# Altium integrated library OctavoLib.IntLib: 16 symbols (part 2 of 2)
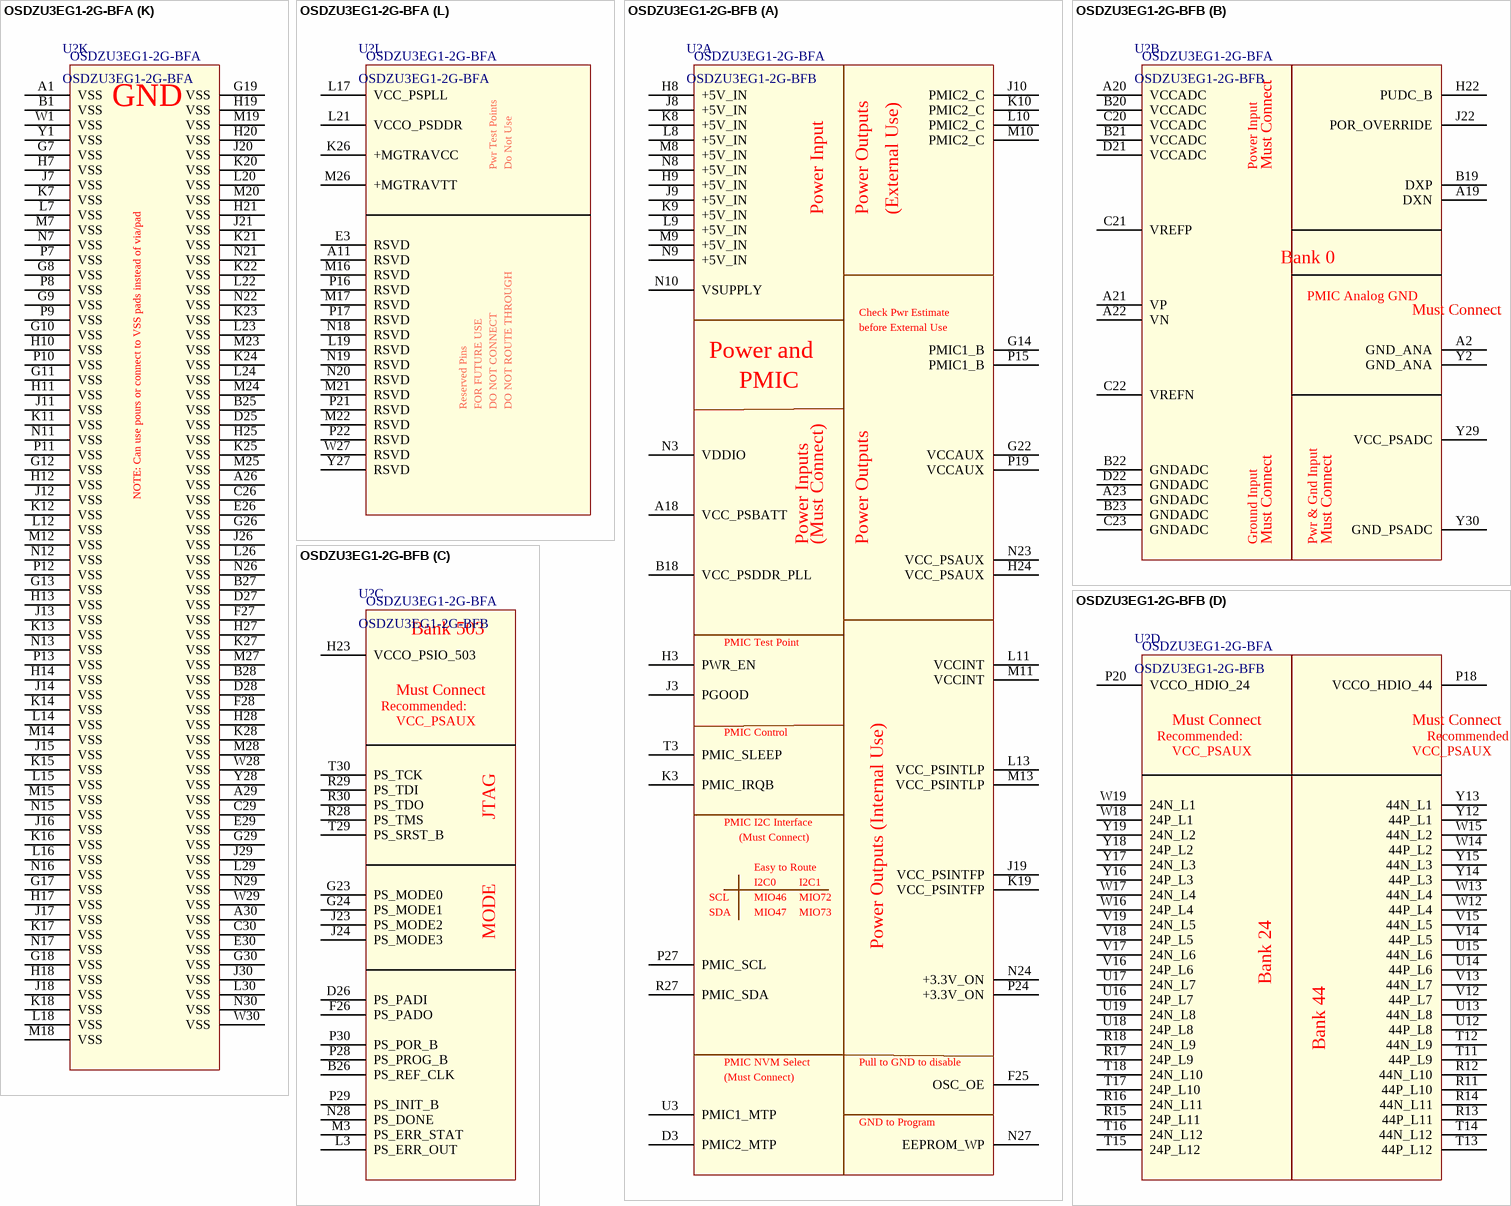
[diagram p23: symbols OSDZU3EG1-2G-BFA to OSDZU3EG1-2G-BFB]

## OSDZU3EG1-2G-BFA
designator U?
Octavo Systems LLC OSDZU3x Family SiP; 20.5mm x 40mm, 1mm pitch 600 pin BGA contains Xilinx XCZU3EG1, 2GB DDR4, two IRPS5401, 32MB QSPI NOR Flash (3.3V), MEMS Oscillator, RTC Crystal and passives; Commercial Temperature (case):  0C to 85C.
footprint BGA_20x30_600_1p00mm (600 pin 1mm pitch footprint)
part A pins: A18 VCC_PSBATT, B18 VCC_PSDDR_PLL, D3 PMIC2_MTP, F25 OSC_OE, G14 PMIC1_B, G22 VCCAUX, H3 PWR_EN, H8 +5V_IN, H9 +5V_IN, H24 VCC_PSAUX, J3 PGOOD, J8 +5V_IN, J9 +5V_IN, J10 PMIC2_C, J19 VCC_PSINTFP, K3 PMIC_IRQB, K8 +5V_IN, K9 +5V_IN, K10 PMIC2_C, K19 VCC_PSINTFP, L8 +5V_IN, L9 +5V_IN, L10 PMIC2_C, L11 VCCINT, L13 VCC_PSINTLP, M8 +5V_IN, M9 +5V_IN, M10 PMIC2_C, M11 VCCINT, M13 VCC_PSINTLP, N3 VDDIO, N8 +5V_IN, N9 +5V_IN, N10 VSUPPLY, N23 VCC_PSAUX, N24 +3.3V_ON, N27 EEPROM_WP, P15 PMIC1_B, P19 VCCAUX, P24 +3.3V_ON, P27 PMIC_SCL, R27 PMIC_SDA, T3 PMIC_SLEEP, U3 PMIC1_MTP
part B pins: A2 GND_ANA, A19 DXN, A20 VCCADC, A21 VP, A22 VN, A23 GNDADC, B19 DXP, B20 VCCADC, B21 VCCADC, B22 GNDADC, B23 GNDADC, C20 VCCADC, C21 VREFP, C22 VREFN, C23 GNDADC, D21 VCCADC, D22 GNDADC, H22 PUDC_B, J22 POR_OVERRIDE, Y2 GND_ANA, Y29 VCC_PSADC, Y30 GND_PSADC
part C pins: B26 PS_REF_CLK, D26 PS_PADI, F26 PS_PADO, G23 PS_MODE0, G24 PS_MODE1, H23 VCCO_PSIO_503, J23 PS_MODE2, J24 PS_MODE3, L3 PS_ERR_OUT, M3 PS_ERR_STAT, N28 PS_DONE, P28 PS_PROG_B, P29 PS_INIT_B, P30 PS_POR_B, R28 PS_TMS, R29 PS_TDI, R30 PS_TDO, T29 PS_SRST_B, T30 PS_TCK
part D pins: P18 VCCO_HDIO_44, P20 VCCO_HDIO_24, R11 44P_L10, R12 44N_L10, R13 44P_L11, R14 44N_L11, R15 24P_L11, R16 24N_L11, R17 24P_L9, R18 24N_L9, T11 44P_L9, T12 44N_L9, T13 44P_L12, T14 44N_L12, T15 24P_L12, T16 24N_L12, T17 24P_L10, T18 24N_L10, U12 44P_L8, U13 44N_L8, U14 44P_L6, U15 44N_L6, U16 24P_L7, U17 24N_L7, U18 24P_L8, U19 24N_L8, V12 44P_L7, V13 44N_L7, V14 44P_L5, V15 44N_L5, V16 24P_L6, V17 24N_L6, V18 24P_L5, V19 24N_L5, W12 44P_L4, W13 44N_L4, W14 44P_L2, W15 44N_L2, W16 24P_L4, W17 24N_L4, W18 24P_L1, W19 24N_L1, Y12 44P_L1, Y13 44N_L1, Y14 44P_L3, Y15 44N_L3, Y16 24P_L3, Y17 24N_L3, Y18 24P_L2, Y19 24N_L2
part E pins: A12 25P_L11, A13 25N_L11, A14 26P_L3, A15 26N_L3, A16 26P_L1, A17 26N_L1, B11 25P_L10, B12 25P_L12, B13 25N_L12, B14 26P_L2, B15 26N_L2, B16 26P_L4, B17 26N_L4, C11 25N_L10, C12 25P_L5, C13 25N_L5, C14 25P_L8, C15 25N_L8, C16 26P_L5, C17 26N_L5, C18 26P_L7, C19 26N_L7, D11 25P_L9, D12 25P_L4, D13 25N_L4, D14 25P_L6, D15 25N_L6, D16 26P_L6, D17 26N_L6, D18 26P_L8, D19 26N_L8, E11 25N_L9, E12 25P_L3, E13 25N_L3, E14 25P_L7, E15 25N_L7, E16 26P_L9, E17 26N_L9, E18 26P_L11, E19 26N_L11, F11 25P_L1, F12 25N_L1, F13 25P_L2, F14 25N_L2, F15 26P_L10, F16 26N_L10, F17 26P_L12, F18 26N_L12, G20 VCCO_HDIO_25, G21 VCCO_HDIO_26
part F pins: A5 65_T3, A6 65P_L19, B5 65_T2, B6 65N_L19, C5 65P_L21, C6 65P_L24, D5 65N_L21, D6 65N_L24, E5 65P_L14, E6 65P_L23, E8 65P_L20, F5 65N_L14, F6 65N_L23, F8 65N_L20, G3 65_T1, G5 65P_L13, G6 65P_L18, G15 VCCO_HPIO_65, H5 65N_L13, H6 65N_L18, H15 VREF_65, J4 65P_L10, J5 64_T0, J6 65P_L17, K4 65N_L10, K5 64_T3, K6 65N_L17, L1 65P_L8, L4 65P_L11, L5 65P_L6, L6 65P_L5, M1 65N_L8, M2 65P_L9, M4 65N_L11, M5 65N_L6, M6 65N_L5, N1 65P_L7, N2 65N_L9, N4 65P_L22, N5 65P_L4, N6 65P_L3, N14 VREF_64, P1 65N_L7, P2 65P_L12, P3 65_T0, P4 65N_L22, P5 65N_L4, P6 65N_L3, P14 VCCO_HPIO_64, R1 64P_L18, R2 65N_L12, R3 64_T2, R4 65P_L15, R5 65P_L2, R6 65P_L1, R7 64P_L6, R8 64P_L5, R9 64P_L3, R10 64P_L11, T1 64N_L18, T2 64P_L17, T4 65N_L15, T5 65N_L2, T6 65N_L1, T7 64N_L6, T8 64N_L5, T9 64N_L3, T10 64N_L11, U1 64P_L24, U2 64N_L17, U4 65P_L16, U5 64P_L14, U6 64P_L15, U7 64P_L13, U8 64P_L4, U9 64P_L1, U10 64P_L12, U11 64P_L2, V1 64N_L24, V2 64P_L16, V3 64_T1, V4 65N_L16, V5 64N_L14, V6 64N_L15, V7 64N_L13, V8 64N_L4, V9 64N_L1, V10 64N_L12, V11 64N_L2, W2 64N_L16, W3 64P_L23, W4 64P_L22, W5 64P_L21, W6 64P_L20, W7 64P_L19, W8 64P_L10, W9 64P_L8, W10 64P_L9, W11 64P_L7, Y3 64N_L23, Y4 64N_L22, Y5 64N_L21, Y6 64N_L20, Y7 64N_L19, Y8 64N_L10, Y9 64N_L8, Y10 64N_L9, Y11 64N_L7
part G pins: A3 66P_L10, A4 66P_L19, A7 66P_L21, A8 66P_L13, A9 66P_L23, A10 66P_L18, B2 66P_L9, B3 66N_L10, B4 66N_L19, B7 66N_L21, B8 66N_L13, B9 66N_L23, B10 66N_L18, C1 66P_L8, C2 66N_L9, C3 66_T1, C4 66P_L11, C7 66_T3, C8 66P_L15, C9 66P_L24, C10 66P_L17, D1 66N_L8, D2 66P_L12, D4 66N_L11, D7 66_T2, D8 66N_L15, D9 66N_L24, D10 66N_L17, E1 66P_L7, E2 66N_L12, E4 66P_L14, E7 66P_L20, E9 66P_L22, E10 66P_L16, F1 66N_L7, F2 66P_L5, F3 66_T0, F4 66N_L14, F7 66N_L20, F9 66N_L22, F10 66N_L16, G1 66P_L2, G2 66N_L5, G4 66P_L6, G16 VCCO_HPIO_66, H1 66N_L2, H2 66P_L4, H4 66N_L6, H16 VREF_66, J1 66P_L1, J2 66N_L4, K1 66N_L1, K2 66P_L3, L2 66N_L3
part H pins: J25 VCCO_PSIO_501, P23 VCCO_PSIO_500, R19 MIO30, R20 MIO31, R21 MIO35, R22 MIO38, R23 MIO39, R24 MIO41, T19 MIO29, T20 MIO27, T21 MIO32, T22 MIO37, T23 MIO36, T24 MIO40, T25 MIO44, T26 MIO46, T27 MIO45, T28 MIO48, U20 MIO28, U21 MIO26, U22 MIO33, U23 MIO34, U24 MIO42, U25 MIO43, U26 MIO47, U27 MIO51, U28 MIO49, U29 MIO50, U30 MIO25, V20 MIO2, V21 MIO6, V22 MIO8, V23 MIO9, V24 MIO11, V25 MIO23, V26 MIO24, V27 MIO20, V28 MIO18, V29 MIO22, V30 MIO21, W20 MIO0, W21 MIO1, W22 MIO7, W23 MIO5, W24 MIO15, W25 MIO12, W26 MIO17, Y20 MIO3, Y21 MIO4, Y22 MIO13, Y23 MIO14, Y24 MIO16, Y25 MIO10, Y26 MIO19
part I pins: A24 MIO65, A25 MIO75, B24 MIO67, C24 MIO70, C25 MIO71, D20 MIO57, D23 MIO62, D24 MIO68, E20 MIO55, E21 MIO59, E22 MIO60, E23 MIO69, E24 MIO74, E25 MIO76, F19 MIO56, F20 MIO53, F21 MIO54, F22 MIO61, F23 MIO63, F24 MIO64, G25 VCCO_PSIO_502, L25 MIO58, N25 MIO77, P25 MIO52, P26 MIO72, R25 MIO66, R26 MIO73
part J pins: A27 GTRX_TX_P3, A28 GTRX_TX_N3, B29 GTRX_CLK_P3, B30 GTRX_CLK_N3, C27 GTRX_RX_P3, C28 GTRX_RX_N3, D29 GTRX_RX_P2, D30 GTRX_RX_N2, E27 GTRX_CLK_P2, E28 GTRX_CLK_N2, F29 GTRX_TX_P2, F30 GTRX_TX_N2, G27 GTRX_TX_P1, G28 GTRX_TX_N1, H26 PS_MGTRREF, H29 GTRX_CLK_P1, H30 GTRX_CLK_N1, J27 GTRX_RX_P1, J28 GTRX_RX_N1, K29 GTRX_RX_P0, K30 GTRX_RX_N0, L27 GTRX_CLK_P0, L28 GTRX_CLK_N0, M29 GTRX_TX_P0, M30 GTRX_TX_N0
part K pins: A1 VSS, A26 VSS, A29 VSS, A30 VSS, B1 VSS, B25 VSS, B27 VSS, B28 VSS, C26 VSS, C29 VSS, C30 VSS, D25 VSS, D27 VSS, D28 VSS, E26 VSS, E29 VSS, E30 VSS, F27 VSS, F28 VSS, G7 VSS, G8 VSS, G9 VSS, G10 VSS, G11 VSS, G12 VSS, G13 VSS, G17 VSS, G18 VSS, G19 VSS, G26 VSS, G29 VSS, G30 VSS, H7 VSS, H10 VSS, H11 VSS, H12 VSS, H13 VSS, H14 VSS, H17 VSS, H18 VSS, H19 VSS, H20 VSS, H21 VSS, H25 VSS, H27 VSS, H28 VSS, J7 VSS, J11 VSS, J12 VSS, J13 VSS, J14 VSS, J15 VSS, J16 VSS, J17 VSS, J18 VSS, J20 VSS, J21 VSS, J26 VSS, J29 VSS, J30 VSS, K7 VSS, K11 VSS, K12 VSS, K13 VSS, K14 VSS, K15 VSS, K16 VSS, K17 VSS, K18 VSS, K20 VSS, K21 VSS, K22 VSS, K23 VSS, K24 VSS, K25 VSS, K27 VSS, K28 VSS, L7 VSS, L12 VSS, L14 VSS, L15 VSS, L16 VSS, L18 VSS, L20 VSS, L22 VSS, L23 VSS, L24 VSS, L26 VSS, L29 VSS, L30 VSS, M7 VSS, M12 VSS, M14 VSS, M15 VSS, M18 VSS, M19 VSS, M20 VSS, M23 VSS, M24 VSS, M25 VSS, M27 VSS, M28 VSS, N7 VSS, N11 VSS, N12 VSS, N13 VSS, N15 VSS, N16 VSS, N17 VSS, N21 VSS, N22 VSS, N26 VSS, N29 VSS, N30 VSS, P7 VSS, P8 VSS, P9 VSS, P10 VSS, P11 VSS, P12 VSS, P13 VSS, W1 VSS, W28 VSS, W29 VSS, W30 VSS, Y1 VSS, Y28 VSS
part L pins: A11 RSVD, E3 RSVD, K26 +MGTRAVCC, L17 VCC_PSPLL, L19 RSVD, L21 VCCO_PSDDR, M16 RSVD, M17 RSVD, M21 RSVD, M22 RSVD, M26 +MGTRAVTT, N18 RSVD, N19 RSVD, N20 RSVD, P16 RSVD, P17 RSVD, P21 RSVD, P22 RSVD, W27 RSVD, Y27 RSVD

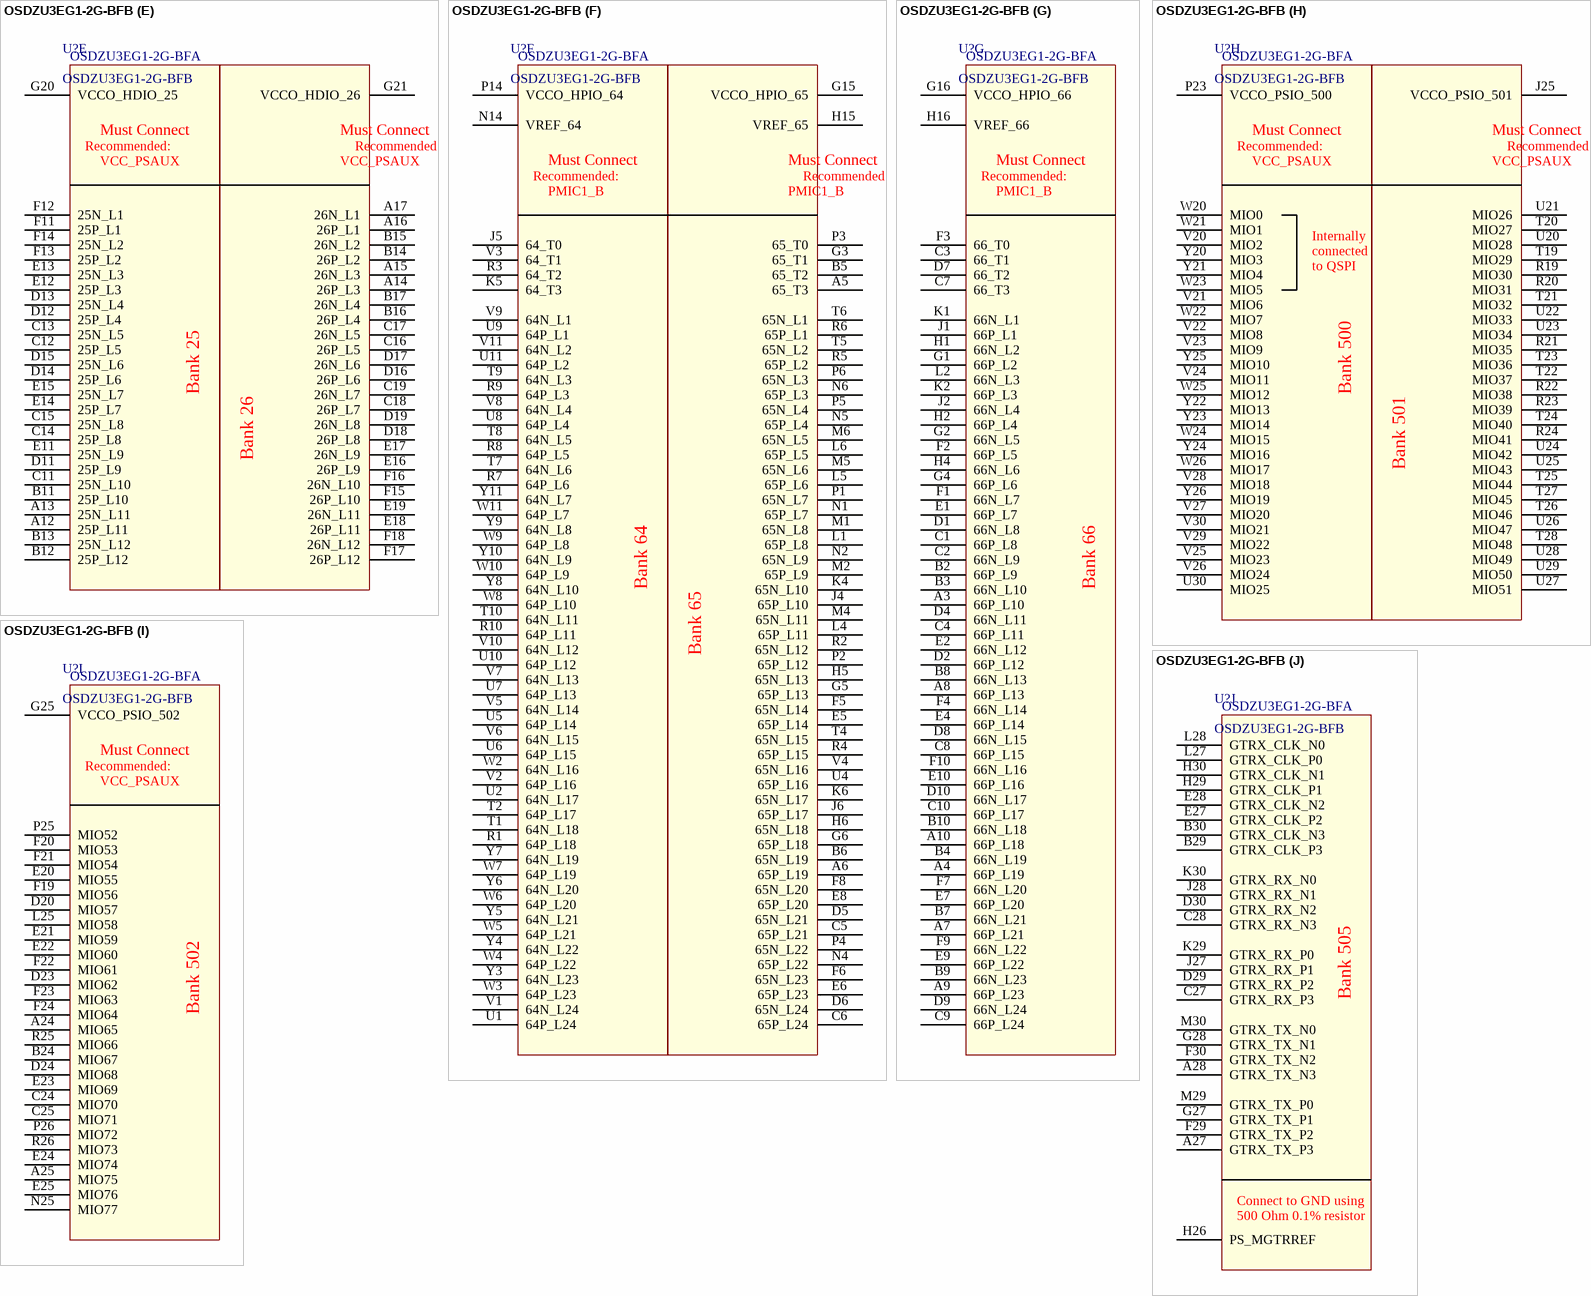
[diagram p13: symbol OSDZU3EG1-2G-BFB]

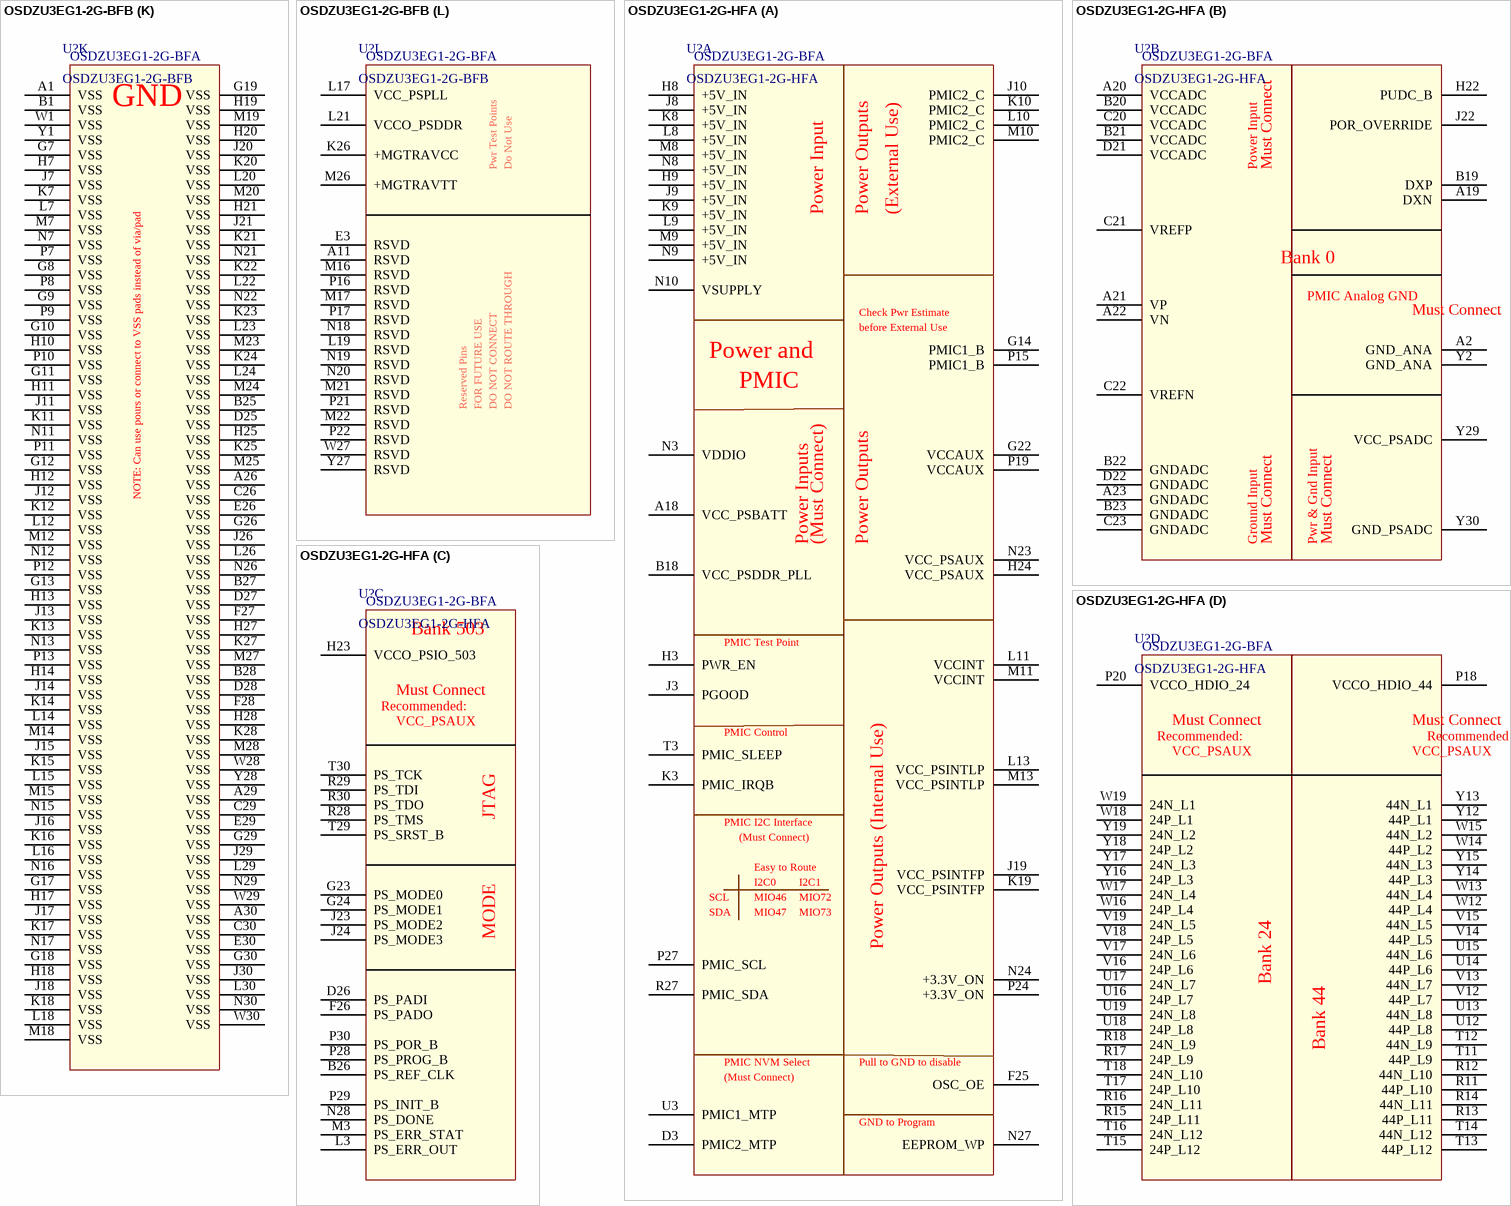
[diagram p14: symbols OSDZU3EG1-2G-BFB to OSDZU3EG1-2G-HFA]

## OSDZU3EG1-2G-BFB
designator U?  PartNumber: OSDZU3EG1-2G-BFA
Octavo Systems LLC OSDZU3x Family SiP; 20.5mm x 40mm, 1mm pitch 600 pin BGA contains Xilinx XCZU3EG1, 2GB DDR4, two IRPS5401, 32MB QSPI NOR Flash (1.8V), MEMS Oscillator, RTC Crystal and passives; Commercial Temperature (case):  0C to 85C.
footprint BGA_20x30_600_1p00mm (600 pin 1mm pitch footprint)
part A pins: A18 VCC_PSBATT, B18 VCC_PSDDR_PLL, D3 PMIC2_MTP, F25 OSC_OE, G14 PMIC1_B, G22 VCCAUX, H3 PWR_EN, H8 +5V_IN, H9 +5V_IN, H24 VCC_PSAUX, J3 PGOOD, J8 +5V_IN, J9 +5V_IN, J10 PMIC2_C, J19 VCC_PSINTFP, K3 PMIC_IRQB, K8 +5V_IN, K9 +5V_IN, K10 PMIC2_C, K19 VCC_PSINTFP, L8 +5V_IN, L9 +5V_IN, L10 PMIC2_C, L11 VCCINT, L13 VCC_PSINTLP, M8 +5V_IN, M9 +5V_IN, M10 PMIC2_C, M11 VCCINT, M13 VCC_PSINTLP, N3 VDDIO, N8 +5V_IN, N9 +5V_IN, N10 VSUPPLY, N23 VCC_PSAUX, N24 +3.3V_ON, N27 EEPROM_WP, P15 PMIC1_B, P19 VCCAUX, P24 +3.3V_ON, P27 PMIC_SCL, R27 PMIC_SDA, T3 PMIC_SLEEP, U3 PMIC1_MTP
part B pins: A2 GND_ANA, A19 DXN, A20 VCCADC, A21 VP, A22 VN, A23 GNDADC, B19 DXP, B20 VCCADC, B21 VCCADC, B22 GNDADC, B23 GNDADC, C20 VCCADC, C21 VREFP, C22 VREFN, C23 GNDADC, D21 VCCADC, D22 GNDADC, H22 PUDC_B, J22 POR_OVERRIDE, Y2 GND_ANA, Y29 VCC_PSADC, Y30 GND_PSADC
part C pins: B26 PS_REF_CLK, D26 PS_PADI, F26 PS_PADO, G23 PS_MODE0, G24 PS_MODE1, H23 VCCO_PSIO_503, J23 PS_MODE2, J24 PS_MODE3, L3 PS_ERR_OUT, M3 PS_ERR_STAT, N28 PS_DONE, P28 PS_PROG_B, P29 PS_INIT_B, P30 PS_POR_B, R28 PS_TMS, R29 PS_TDI, R30 PS_TDO, T29 PS_SRST_B, T30 PS_TCK
part D pins: P18 VCCO_HDIO_44, P20 VCCO_HDIO_24, R11 44P_L10, R12 44N_L10, R13 44P_L11, R14 44N_L11, R15 24P_L11, R16 24N_L11, R17 24P_L9, R18 24N_L9, T11 44P_L9, T12 44N_L9, T13 44P_L12, T14 44N_L12, T15 24P_L12, T16 24N_L12, T17 24P_L10, T18 24N_L10, U12 44P_L8, U13 44N_L8, U14 44P_L6, U15 44N_L6, U16 24P_L7, U17 24N_L7, U18 24P_L8, U19 24N_L8, V12 44P_L7, V13 44N_L7, V14 44P_L5, V15 44N_L5, V16 24P_L6, V17 24N_L6, V18 24P_L5, V19 24N_L5, W12 44P_L4, W13 44N_L4, W14 44P_L2, W15 44N_L2, W16 24P_L4, W17 24N_L4, W18 24P_L1, W19 24N_L1, Y12 44P_L1, Y13 44N_L1, Y14 44P_L3, Y15 44N_L3, Y16 24P_L3, Y17 24N_L3, Y18 24P_L2, Y19 24N_L2
part E pins: A12 25P_L11, A13 25N_L11, A14 26P_L3, A15 26N_L3, A16 26P_L1, A17 26N_L1, B11 25P_L10, B12 25P_L12, B13 25N_L12, B14 26P_L2, B15 26N_L2, B16 26P_L4, B17 26N_L4, C11 25N_L10, C12 25P_L5, C13 25N_L5, C14 25P_L8, C15 25N_L8, C16 26P_L5, C17 26N_L5, C18 26P_L7, C19 26N_L7, D11 25P_L9, D12 25P_L4, D13 25N_L4, D14 25P_L6, D15 25N_L6, D16 26P_L6, D17 26N_L6, D18 26P_L8, D19 26N_L8, E11 25N_L9, E12 25P_L3, E13 25N_L3, E14 25P_L7, E15 25N_L7, E16 26P_L9, E17 26N_L9, E18 26P_L11, E19 26N_L11, F11 25P_L1, F12 25N_L1, F13 25P_L2, F14 25N_L2, F15 26P_L10, F16 26N_L10, F17 26P_L12, F18 26N_L12, G20 VCCO_HDIO_25, G21 VCCO_HDIO_26
part F pins: A5 65_T3, A6 65P_L19, B5 65_T2, B6 65N_L19, C5 65P_L21, C6 65P_L24, D5 65N_L21, D6 65N_L24, E5 65P_L14, E6 65P_L23, E8 65P_L20, F5 65N_L14, F6 65N_L23, F8 65N_L20, G3 65_T1, G5 65P_L13, G6 65P_L18, G15 VCCO_HPIO_65, H5 65N_L13, H6 65N_L18, H15 VREF_65, J4 65P_L10, J5 64_T0, J6 65P_L17, K4 65N_L10, K5 64_T3, K6 65N_L17, L1 65P_L8, L4 65P_L11, L5 65P_L6, L6 65P_L5, M1 65N_L8, M2 65P_L9, M4 65N_L11, M5 65N_L6, M6 65N_L5, N1 65P_L7, N2 65N_L9, N4 65P_L22, N5 65P_L4, N6 65P_L3, N14 VREF_64, P1 65N_L7, P2 65P_L12, P3 65_T0, P4 65N_L22, P5 65N_L4, P6 65N_L3, P14 VCCO_HPIO_64, R1 64P_L18, R2 65N_L12, R3 64_T2, R4 65P_L15, R5 65P_L2, R6 65P_L1, R7 64P_L6, R8 64P_L5, R9 64P_L3, R10 64P_L11, T1 64N_L18, T2 64P_L17, T4 65N_L15, T5 65N_L2, T6 65N_L1, T7 64N_L6, T8 64N_L5, T9 64N_L3, T10 64N_L11, U1 64P_L24, U2 64N_L17, U4 65P_L16, U5 64P_L14, U6 64P_L15, U7 64P_L13, U8 64P_L4, U9 64P_L1, U10 64P_L12, U11 64P_L2, V1 64N_L24, V2 64P_L16, V3 64_T1, V4 65N_L16, V5 64N_L14, V6 64N_L15, V7 64N_L13, V8 64N_L4, V9 64N_L1, V10 64N_L12, V11 64N_L2, W2 64N_L16, W3 64P_L23, W4 64P_L22, W5 64P_L21, W6 64P_L20, W7 64P_L19, W8 64P_L10, W9 64P_L8, W10 64P_L9, W11 64P_L7, Y3 64N_L23, Y4 64N_L22, Y5 64N_L21, Y6 64N_L20, Y7 64N_L19, Y8 64N_L10, Y9 64N_L8, Y10 64N_L9, Y11 64N_L7
part G pins: A3 66P_L10, A4 66P_L19, A7 66P_L21, A8 66P_L13, A9 66P_L23, A10 66P_L18, B2 66P_L9, B3 66N_L10, B4 66N_L19, B7 66N_L21, B8 66N_L13, B9 66N_L23, B10 66N_L18, C1 66P_L8, C2 66N_L9, C3 66_T1, C4 66P_L11, C7 66_T3, C8 66P_L15, C9 66P_L24, C10 66P_L17, D1 66N_L8, D2 66P_L12, D4 66N_L11, D7 66_T2, D8 66N_L15, D9 66N_L24, D10 66N_L17, E1 66P_L7, E2 66N_L12, E4 66P_L14, E7 66P_L20, E9 66P_L22, E10 66P_L16, F1 66N_L7, F2 66P_L5, F3 66_T0, F4 66N_L14, F7 66N_L20, F9 66N_L22, F10 66N_L16, G1 66P_L2, G2 66N_L5, G4 66P_L6, G16 VCCO_HPIO_66, H1 66N_L2, H2 66P_L4, H4 66N_L6, H16 VREF_66, J1 66P_L1, J2 66N_L4, K1 66N_L1, K2 66P_L3, L2 66N_L3
part H pins: J25 VCCO_PSIO_501, P23 VCCO_PSIO_500, R19 MIO30, R20 MIO31, R21 MIO35, R22 MIO38, R23 MIO39, R24 MIO41, T19 MIO29, T20 MIO27, T21 MIO32, T22 MIO37, T23 MIO36, T24 MIO40, T25 MIO44, T26 MIO46, T27 MIO45, T28 MIO48, U20 MIO28, U21 MIO26, U22 MIO33, U23 MIO34, U24 MIO42, U25 MIO43, U26 MIO47, U27 MIO51, U28 MIO49, U29 MIO50, U30 MIO25, V20 MIO2, V21 MIO6, V22 MIO8, V23 MIO9, V24 MIO11, V25 MIO23, V26 MIO24, V27 MIO20, V28 MIO18, V29 MIO22, V30 MIO21, W20 MIO0, W21 MIO1, W22 MIO7, W23 MIO5, W24 MIO15, W25 MIO12, W26 MIO17, Y20 MIO3, Y21 MIO4, Y22 MIO13, Y23 MIO14, Y24 MIO16, Y25 MIO10, Y26 MIO19
part I pins: A24 MIO65, A25 MIO75, B24 MIO67, C24 MIO70, C25 MIO71, D20 MIO57, D23 MIO62, D24 MIO68, E20 MIO55, E21 MIO59, E22 MIO60, E23 MIO69, E24 MIO74, E25 MIO76, F19 MIO56, F20 MIO53, F21 MIO54, F22 MIO61, F23 MIO63, F24 MIO64, G25 VCCO_PSIO_502, L25 MIO58, N25 MIO77, P25 MIO52, P26 MIO72, R25 MIO66, R26 MIO73
part J pins: A27 GTRX_TX_P3, A28 GTRX_TX_N3, B29 GTRX_CLK_P3, B30 GTRX_CLK_N3, C27 GTRX_RX_P3, C28 GTRX_RX_N3, D29 GTRX_RX_P2, D30 GTRX_RX_N2, E27 GTRX_CLK_P2, E28 GTRX_CLK_N2, F29 GTRX_TX_P2, F30 GTRX_TX_N2, G27 GTRX_TX_P1, G28 GTRX_TX_N1, H26 PS_MGTRREF, H29 GTRX_CLK_P1, H30 GTRX_CLK_N1, J27 GTRX_RX_P1, J28 GTRX_RX_N1, K29 GTRX_RX_P0, K30 GTRX_RX_N0, L27 GTRX_CLK_P0, L28 GTRX_CLK_N0, M29 GTRX_TX_P0, M30 GTRX_TX_N0
part K pins: A1 VSS, A26 VSS, A29 VSS, A30 VSS, B1 VSS, B25 VSS, B27 VSS, B28 VSS, C26 VSS, C29 VSS, C30 VSS, D25 VSS, D27 VSS, D28 VSS, E26 VSS, E29 VSS, E30 VSS, F27 VSS, F28 VSS, G7 VSS, G8 VSS, G9 VSS, G10 VSS, G11 VSS, G12 VSS, G13 VSS, G17 VSS, G18 VSS, G19 VSS, G26 VSS, G29 VSS, G30 VSS, H7 VSS, H10 VSS, H11 VSS, H12 VSS, H13 VSS, H14 VSS, H17 VSS, H18 VSS, H19 VSS, H20 VSS, H21 VSS, H25 VSS, H27 VSS, H28 VSS, J7 VSS, J11 VSS, J12 VSS, J13 VSS, J14 VSS, J15 VSS, J16 VSS, J17 VSS, J18 VSS, J20 VSS, J21 VSS, J26 VSS, J29 VSS, J30 VSS, K7 VSS, K11 VSS, K12 VSS, K13 VSS, K14 VSS, K15 VSS, K16 VSS, K17 VSS, K18 VSS, K20 VSS, K21 VSS, K22 VSS, K23 VSS, K24 VSS, K25 VSS, K27 VSS, K28 VSS, L7 VSS, L12 VSS, L14 VSS, L15 VSS, L16 VSS, L18 VSS, L20 VSS, L22 VSS, L23 VSS, L24 VSS, L26 VSS, L29 VSS, L30 VSS, M7 VSS, M12 VSS, M14 VSS, M15 VSS, M18 VSS, M19 VSS, M20 VSS, M23 VSS, M24 VSS, M25 VSS, M27 VSS, M28 VSS, N7 VSS, N11 VSS, N12 VSS, N13 VSS, N15 VSS, N16 VSS, N17 VSS, N21 VSS, N22 VSS, N26 VSS, N29 VSS, N30 VSS, P7 VSS, P8 VSS, P9 VSS, P10 VSS, P11 VSS, P12 VSS, P13 VSS, W1 VSS, W28 VSS, W29 VSS, W30 VSS, Y1 VSS, Y28 VSS
part L pins: A11 RSVD, E3 RSVD, K26 +MGTRAVCC, L17 VCC_PSPLL, L19 RSVD, L21 VCCO_PSDDR, M16 RSVD, M17 RSVD, M21 RSVD, M22 RSVD, M26 +MGTRAVTT, N18 RSVD, N19 RSVD, N20 RSVD, P16 RSVD, P17 RSVD, P21 RSVD, P22 RSVD, W27 RSVD, Y27 RSVD

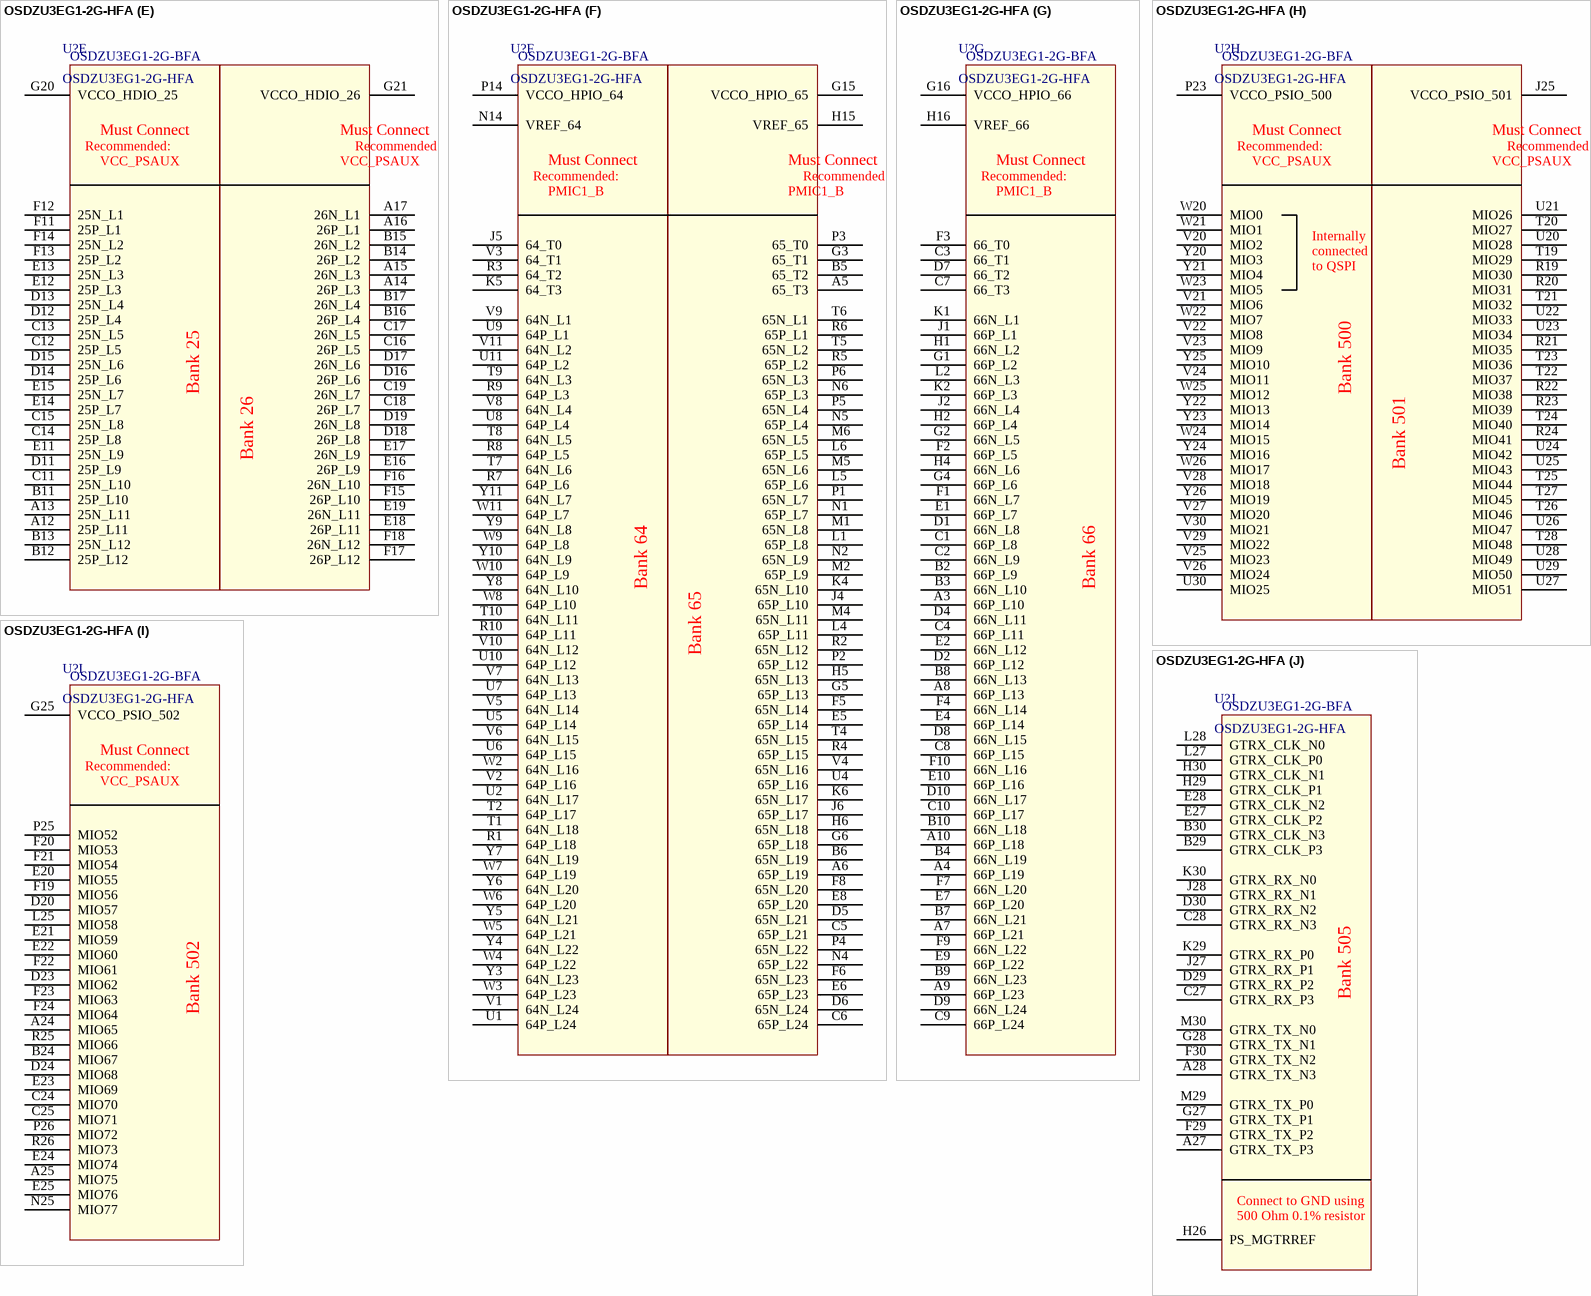
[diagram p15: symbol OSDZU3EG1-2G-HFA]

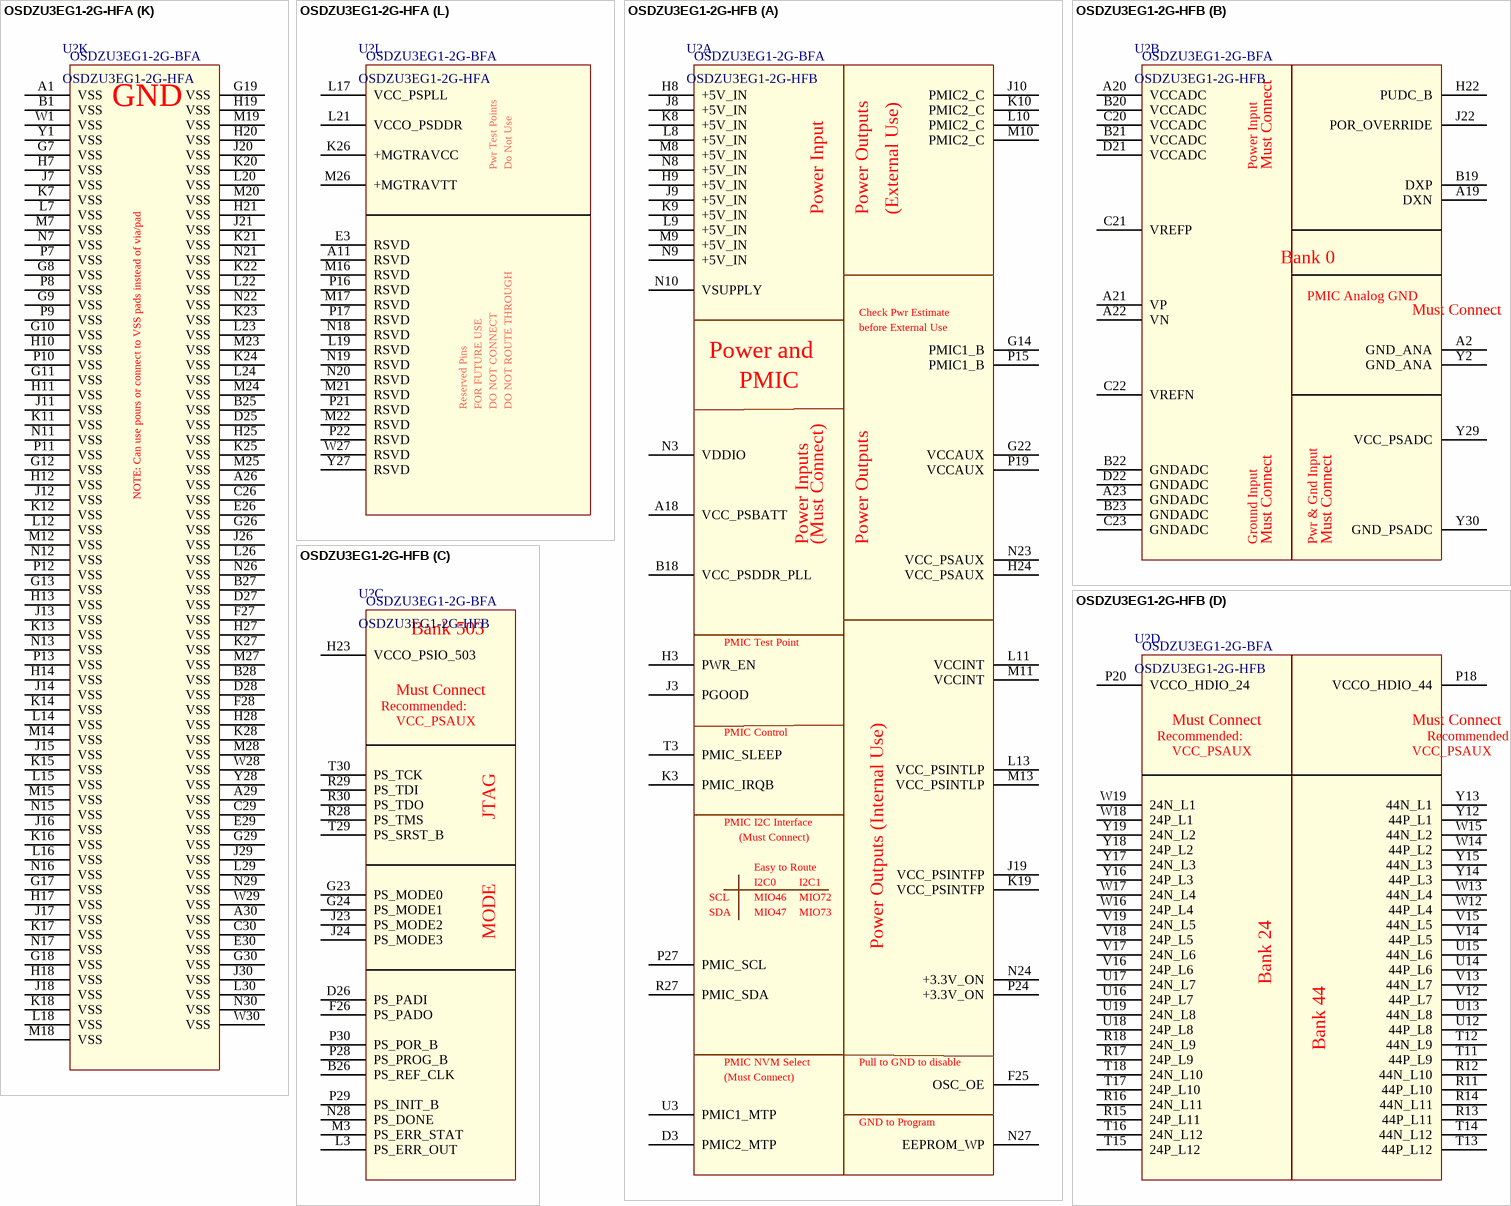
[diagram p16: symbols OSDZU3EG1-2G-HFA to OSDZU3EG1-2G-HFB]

## OSDZU3EG1-2G-HFA
designator U?  PartNumber: OSDZU3EG1-2G-BFA
Octavo Systems LLC OSDZU3x Family SiP; 20.5mm x 40mm, 1mm pitch 600 pin BGA contains Xilinx XCZU3EG1, 2GB DDR4, two IRPS5401, 32MB QSPI NOR Flash (3.3V), MEMS Oscillator, RTC Crystal and passives; Industrial Extended High Temperature (case):  -40C to 100C.
footprint BGA_20x30_600_1p00mm (600 pin 1mm pitch footprint)
part A pins: A18 VCC_PSBATT, B18 VCC_PSDDR_PLL, D3 PMIC2_MTP, F25 OSC_OE, G14 PMIC1_B, G22 VCCAUX, H3 PWR_EN, H8 +5V_IN, H9 +5V_IN, H24 VCC_PSAUX, J3 PGOOD, J8 +5V_IN, J9 +5V_IN, J10 PMIC2_C, J19 VCC_PSINTFP, K3 PMIC_IRQB, K8 +5V_IN, K9 +5V_IN, K10 PMIC2_C, K19 VCC_PSINTFP, L8 +5V_IN, L9 +5V_IN, L10 PMIC2_C, L11 VCCINT, L13 VCC_PSINTLP, M8 +5V_IN, M9 +5V_IN, M10 PMIC2_C, M11 VCCINT, M13 VCC_PSINTLP, N3 VDDIO, N8 +5V_IN, N9 +5V_IN, N10 VSUPPLY, N23 VCC_PSAUX, N24 +3.3V_ON, N27 EEPROM_WP, P15 PMIC1_B, P19 VCCAUX, P24 +3.3V_ON, P27 PMIC_SCL, R27 PMIC_SDA, T3 PMIC_SLEEP, U3 PMIC1_MTP
part B pins: A2 GND_ANA, A19 DXN, A20 VCCADC, A21 VP, A22 VN, A23 GNDADC, B19 DXP, B20 VCCADC, B21 VCCADC, B22 GNDADC, B23 GNDADC, C20 VCCADC, C21 VREFP, C22 VREFN, C23 GNDADC, D21 VCCADC, D22 GNDADC, H22 PUDC_B, J22 POR_OVERRIDE, Y2 GND_ANA, Y29 VCC_PSADC, Y30 GND_PSADC
part C pins: B26 PS_REF_CLK, D26 PS_PADI, F26 PS_PADO, G23 PS_MODE0, G24 PS_MODE1, H23 VCCO_PSIO_503, J23 PS_MODE2, J24 PS_MODE3, L3 PS_ERR_OUT, M3 PS_ERR_STAT, N28 PS_DONE, P28 PS_PROG_B, P29 PS_INIT_B, P30 PS_POR_B, R28 PS_TMS, R29 PS_TDI, R30 PS_TDO, T29 PS_SRST_B, T30 PS_TCK
part D pins: P18 VCCO_HDIO_44, P20 VCCO_HDIO_24, R11 44P_L10, R12 44N_L10, R13 44P_L11, R14 44N_L11, R15 24P_L11, R16 24N_L11, R17 24P_L9, R18 24N_L9, T11 44P_L9, T12 44N_L9, T13 44P_L12, T14 44N_L12, T15 24P_L12, T16 24N_L12, T17 24P_L10, T18 24N_L10, U12 44P_L8, U13 44N_L8, U14 44P_L6, U15 44N_L6, U16 24P_L7, U17 24N_L7, U18 24P_L8, U19 24N_L8, V12 44P_L7, V13 44N_L7, V14 44P_L5, V15 44N_L5, V16 24P_L6, V17 24N_L6, V18 24P_L5, V19 24N_L5, W12 44P_L4, W13 44N_L4, W14 44P_L2, W15 44N_L2, W16 24P_L4, W17 24N_L4, W18 24P_L1, W19 24N_L1, Y12 44P_L1, Y13 44N_L1, Y14 44P_L3, Y15 44N_L3, Y16 24P_L3, Y17 24N_L3, Y18 24P_L2, Y19 24N_L2
part E pins: A12 25P_L11, A13 25N_L11, A14 26P_L3, A15 26N_L3, A16 26P_L1, A17 26N_L1, B11 25P_L10, B12 25P_L12, B13 25N_L12, B14 26P_L2, B15 26N_L2, B16 26P_L4, B17 26N_L4, C11 25N_L10, C12 25P_L5, C13 25N_L5, C14 25P_L8, C15 25N_L8, C16 26P_L5, C17 26N_L5, C18 26P_L7, C19 26N_L7, D11 25P_L9, D12 25P_L4, D13 25N_L4, D14 25P_L6, D15 25N_L6, D16 26P_L6, D17 26N_L6, D18 26P_L8, D19 26N_L8, E11 25N_L9, E12 25P_L3, E13 25N_L3, E14 25P_L7, E15 25N_L7, E16 26P_L9, E17 26N_L9, E18 26P_L11, E19 26N_L11, F11 25P_L1, F12 25N_L1, F13 25P_L2, F14 25N_L2, F15 26P_L10, F16 26N_L10, F17 26P_L12, F18 26N_L12, G20 VCCO_HDIO_25, G21 VCCO_HDIO_26
part F pins: A5 65_T3, A6 65P_L19, B5 65_T2, B6 65N_L19, C5 65P_L21, C6 65P_L24, D5 65N_L21, D6 65N_L24, E5 65P_L14, E6 65P_L23, E8 65P_L20, F5 65N_L14, F6 65N_L23, F8 65N_L20, G3 65_T1, G5 65P_L13, G6 65P_L18, G15 VCCO_HPIO_65, H5 65N_L13, H6 65N_L18, H15 VREF_65, J4 65P_L10, J5 64_T0, J6 65P_L17, K4 65N_L10, K5 64_T3, K6 65N_L17, L1 65P_L8, L4 65P_L11, L5 65P_L6, L6 65P_L5, M1 65N_L8, M2 65P_L9, M4 65N_L11, M5 65N_L6, M6 65N_L5, N1 65P_L7, N2 65N_L9, N4 65P_L22, N5 65P_L4, N6 65P_L3, N14 VREF_64, P1 65N_L7, P2 65P_L12, P3 65_T0, P4 65N_L22, P5 65N_L4, P6 65N_L3, P14 VCCO_HPIO_64, R1 64P_L18, R2 65N_L12, R3 64_T2, R4 65P_L15, R5 65P_L2, R6 65P_L1, R7 64P_L6, R8 64P_L5, R9 64P_L3, R10 64P_L11, T1 64N_L18, T2 64P_L17, T4 65N_L15, T5 65N_L2, T6 65N_L1, T7 64N_L6, T8 64N_L5, T9 64N_L3, T10 64N_L11, U1 64P_L24, U2 64N_L17, U4 65P_L16, U5 64P_L14, U6 64P_L15, U7 64P_L13, U8 64P_L4, U9 64P_L1, U10 64P_L12, U11 64P_L2, V1 64N_L24, V2 64P_L16, V3 64_T1, V4 65N_L16, V5 64N_L14, V6 64N_L15, V7 64N_L13, V8 64N_L4, V9 64N_L1, V10 64N_L12, V11 64N_L2, W2 64N_L16, W3 64P_L23, W4 64P_L22, W5 64P_L21, W6 64P_L20, W7 64P_L19, W8 64P_L10, W9 64P_L8, W10 64P_L9, W11 64P_L7, Y3 64N_L23, Y4 64N_L22, Y5 64N_L21, Y6 64N_L20, Y7 64N_L19, Y8 64N_L10, Y9 64N_L8, Y10 64N_L9, Y11 64N_L7
part G pins: A3 66P_L10, A4 66P_L19, A7 66P_L21, A8 66P_L13, A9 66P_L23, A10 66P_L18, B2 66P_L9, B3 66N_L10, B4 66N_L19, B7 66N_L21, B8 66N_L13, B9 66N_L23, B10 66N_L18, C1 66P_L8, C2 66N_L9, C3 66_T1, C4 66P_L11, C7 66_T3, C8 66P_L15, C9 66P_L24, C10 66P_L17, D1 66N_L8, D2 66P_L12, D4 66N_L11, D7 66_T2, D8 66N_L15, D9 66N_L24, D10 66N_L17, E1 66P_L7, E2 66N_L12, E4 66P_L14, E7 66P_L20, E9 66P_L22, E10 66P_L16, F1 66N_L7, F2 66P_L5, F3 66_T0, F4 66N_L14, F7 66N_L20, F9 66N_L22, F10 66N_L16, G1 66P_L2, G2 66N_L5, G4 66P_L6, G16 VCCO_HPIO_66, H1 66N_L2, H2 66P_L4, H4 66N_L6, H16 VREF_66, J1 66P_L1, J2 66N_L4, K1 66N_L1, K2 66P_L3, L2 66N_L3
part H pins: J25 VCCO_PSIO_501, P23 VCCO_PSIO_500, R19 MIO30, R20 MIO31, R21 MIO35, R22 MIO38, R23 MIO39, R24 MIO41, T19 MIO29, T20 MIO27, T21 MIO32, T22 MIO37, T23 MIO36, T24 MIO40, T25 MIO44, T26 MIO46, T27 MIO45, T28 MIO48, U20 MIO28, U21 MIO26, U22 MIO33, U23 MIO34, U24 MIO42, U25 MIO43, U26 MIO47, U27 MIO51, U28 MIO49, U29 MIO50, U30 MIO25, V20 MIO2, V21 MIO6, V22 MIO8, V23 MIO9, V24 MIO11, V25 MIO23, V26 MIO24, V27 MIO20, V28 MIO18, V29 MIO22, V30 MIO21, W20 MIO0, W21 MIO1, W22 MIO7, W23 MIO5, W24 MIO15, W25 MIO12, W26 MIO17, Y20 MIO3, Y21 MIO4, Y22 MIO13, Y23 MIO14, Y24 MIO16, Y25 MIO10, Y26 MIO19
part I pins: A24 MIO65, A25 MIO75, B24 MIO67, C24 MIO70, C25 MIO71, D20 MIO57, D23 MIO62, D24 MIO68, E20 MIO55, E21 MIO59, E22 MIO60, E23 MIO69, E24 MIO74, E25 MIO76, F19 MIO56, F20 MIO53, F21 MIO54, F22 MIO61, F23 MIO63, F24 MIO64, G25 VCCO_PSIO_502, L25 MIO58, N25 MIO77, P25 MIO52, P26 MIO72, R25 MIO66, R26 MIO73
part J pins: A27 GTRX_TX_P3, A28 GTRX_TX_N3, B29 GTRX_CLK_P3, B30 GTRX_CLK_N3, C27 GTRX_RX_P3, C28 GTRX_RX_N3, D29 GTRX_RX_P2, D30 GTRX_RX_N2, E27 GTRX_CLK_P2, E28 GTRX_CLK_N2, F29 GTRX_TX_P2, F30 GTRX_TX_N2, G27 GTRX_TX_P1, G28 GTRX_TX_N1, H26 PS_MGTRREF, H29 GTRX_CLK_P1, H30 GTRX_CLK_N1, J27 GTRX_RX_P1, J28 GTRX_RX_N1, K29 GTRX_RX_P0, K30 GTRX_RX_N0, L27 GTRX_CLK_P0, L28 GTRX_CLK_N0, M29 GTRX_TX_P0, M30 GTRX_TX_N0
part K pins: A1 VSS, A26 VSS, A29 VSS, A30 VSS, B1 VSS, B25 VSS, B27 VSS, B28 VSS, C26 VSS, C29 VSS, C30 VSS, D25 VSS, D27 VSS, D28 VSS, E26 VSS, E29 VSS, E30 VSS, F27 VSS, F28 VSS, G7 VSS, G8 VSS, G9 VSS, G10 VSS, G11 VSS, G12 VSS, G13 VSS, G17 VSS, G18 VSS, G19 VSS, G26 VSS, G29 VSS, G30 VSS, H7 VSS, H10 VSS, H11 VSS, H12 VSS, H13 VSS, H14 VSS, H17 VSS, H18 VSS, H19 VSS, H20 VSS, H21 VSS, H25 VSS, H27 VSS, H28 VSS, J7 VSS, J11 VSS, J12 VSS, J13 VSS, J14 VSS, J15 VSS, J16 VSS, J17 VSS, J18 VSS, J20 VSS, J21 VSS, J26 VSS, J29 VSS, J30 VSS, K7 VSS, K11 VSS, K12 VSS, K13 VSS, K14 VSS, K15 VSS, K16 VSS, K17 VSS, K18 VSS, K20 VSS, K21 VSS, K22 VSS, K23 VSS, K24 VSS, K25 VSS, K27 VSS, K28 VSS, L7 VSS, L12 VSS, L14 VSS, L15 VSS, L16 VSS, L18 VSS, L20 VSS, L22 VSS, L23 VSS, L24 VSS, L26 VSS, L29 VSS, L30 VSS, M7 VSS, M12 VSS, M14 VSS, M15 VSS, M18 VSS, M19 VSS, M20 VSS, M23 VSS, M24 VSS, M25 VSS, M27 VSS, M28 VSS, N7 VSS, N11 VSS, N12 VSS, N13 VSS, N15 VSS, N16 VSS, N17 VSS, N21 VSS, N22 VSS, N26 VSS, N29 VSS, N30 VSS, P7 VSS, P8 VSS, P9 VSS, P10 VSS, P11 VSS, P12 VSS, P13 VSS, W1 VSS, W28 VSS, W29 VSS, W30 VSS, Y1 VSS, Y28 VSS
part L pins: A11 RSVD, E3 RSVD, K26 +MGTRAVCC, L17 VCC_PSPLL, L19 RSVD, L21 VCCO_PSDDR, M16 RSVD, M17 RSVD, M21 RSVD, M22 RSVD, M26 +MGTRAVTT, N18 RSVD, N19 RSVD, N20 RSVD, P16 RSVD, P17 RSVD, P21 RSVD, P22 RSVD, W27 RSVD, Y27 RSVD

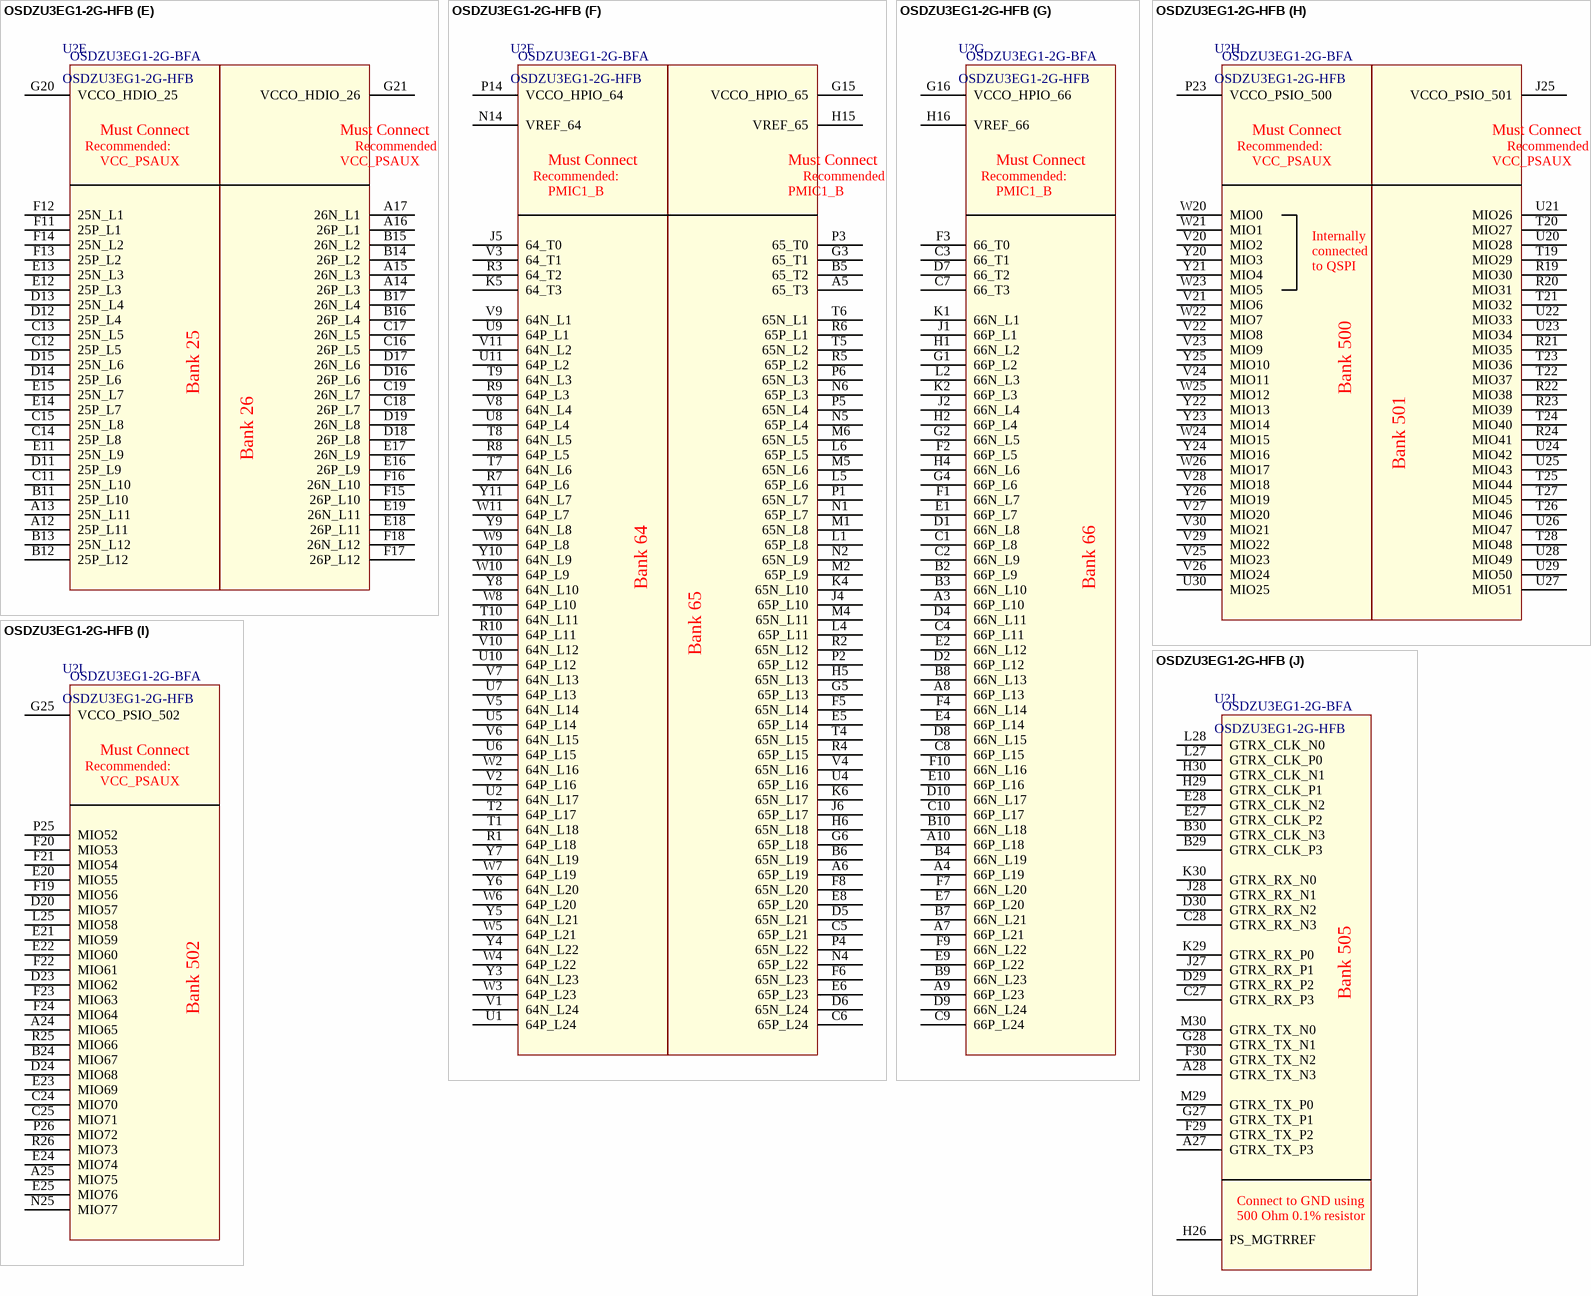
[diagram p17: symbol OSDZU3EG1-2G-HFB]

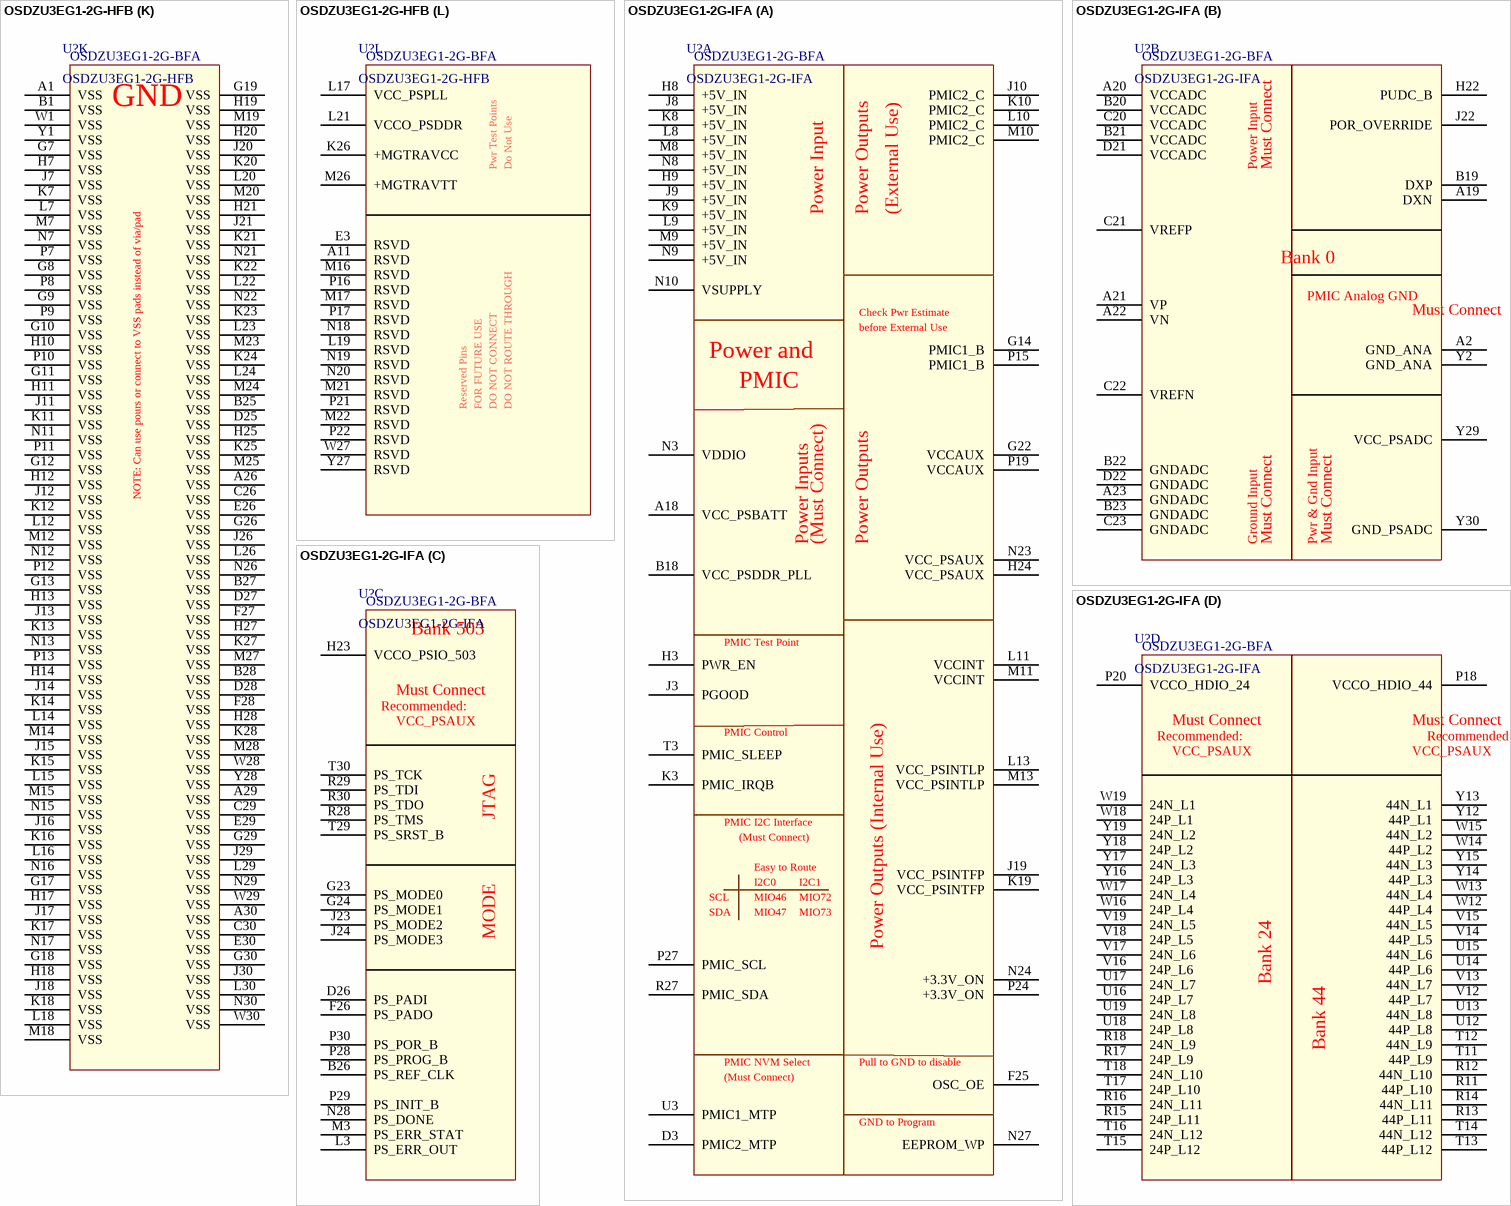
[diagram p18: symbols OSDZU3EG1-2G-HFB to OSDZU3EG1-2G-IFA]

## OSDZU3EG1-2G-HFB
designator U?  PartNumber: OSDZU3EG1-2G-BFA
Octavo Systems LLC OSDZU3x Family SiP; 20.5mm x 40mm, 1mm pitch 600 pin BGA contains Xilinx XCZU3EG1, 2GB DDR4, two IRPS5401, 32MB QSPI NOR Flash (1.8V), MEMS Oscillator, RTC Crystal and passives; Industrial Extended High Temperature (case):  -40C to 100C.
footprint BGA_20x30_600_1p00mm (600 pin 1mm pitch footprint)
part A pins: A18 VCC_PSBATT, B18 VCC_PSDDR_PLL, D3 PMIC2_MTP, F25 OSC_OE, G14 PMIC1_B, G22 VCCAUX, H3 PWR_EN, H8 +5V_IN, H9 +5V_IN, H24 VCC_PSAUX, J3 PGOOD, J8 +5V_IN, J9 +5V_IN, J10 PMIC2_C, J19 VCC_PSINTFP, K3 PMIC_IRQB, K8 +5V_IN, K9 +5V_IN, K10 PMIC2_C, K19 VCC_PSINTFP, L8 +5V_IN, L9 +5V_IN, L10 PMIC2_C, L11 VCCINT, L13 VCC_PSINTLP, M8 +5V_IN, M9 +5V_IN, M10 PMIC2_C, M11 VCCINT, M13 VCC_PSINTLP, N3 VDDIO, N8 +5V_IN, N9 +5V_IN, N10 VSUPPLY, N23 VCC_PSAUX, N24 +3.3V_ON, N27 EEPROM_WP, P15 PMIC1_B, P19 VCCAUX, P24 +3.3V_ON, P27 PMIC_SCL, R27 PMIC_SDA, T3 PMIC_SLEEP, U3 PMIC1_MTP
part B pins: A2 GND_ANA, A19 DXN, A20 VCCADC, A21 VP, A22 VN, A23 GNDADC, B19 DXP, B20 VCCADC, B21 VCCADC, B22 GNDADC, B23 GNDADC, C20 VCCADC, C21 VREFP, C22 VREFN, C23 GNDADC, D21 VCCADC, D22 GNDADC, H22 PUDC_B, J22 POR_OVERRIDE, Y2 GND_ANA, Y29 VCC_PSADC, Y30 GND_PSADC
part C pins: B26 PS_REF_CLK, D26 PS_PADI, F26 PS_PADO, G23 PS_MODE0, G24 PS_MODE1, H23 VCCO_PSIO_503, J23 PS_MODE2, J24 PS_MODE3, L3 PS_ERR_OUT, M3 PS_ERR_STAT, N28 PS_DONE, P28 PS_PROG_B, P29 PS_INIT_B, P30 PS_POR_B, R28 PS_TMS, R29 PS_TDI, R30 PS_TDO, T29 PS_SRST_B, T30 PS_TCK
part D pins: P18 VCCO_HDIO_44, P20 VCCO_HDIO_24, R11 44P_L10, R12 44N_L10, R13 44P_L11, R14 44N_L11, R15 24P_L11, R16 24N_L11, R17 24P_L9, R18 24N_L9, T11 44P_L9, T12 44N_L9, T13 44P_L12, T14 44N_L12, T15 24P_L12, T16 24N_L12, T17 24P_L10, T18 24N_L10, U12 44P_L8, U13 44N_L8, U14 44P_L6, U15 44N_L6, U16 24P_L7, U17 24N_L7, U18 24P_L8, U19 24N_L8, V12 44P_L7, V13 44N_L7, V14 44P_L5, V15 44N_L5, V16 24P_L6, V17 24N_L6, V18 24P_L5, V19 24N_L5, W12 44P_L4, W13 44N_L4, W14 44P_L2, W15 44N_L2, W16 24P_L4, W17 24N_L4, W18 24P_L1, W19 24N_L1, Y12 44P_L1, Y13 44N_L1, Y14 44P_L3, Y15 44N_L3, Y16 24P_L3, Y17 24N_L3, Y18 24P_L2, Y19 24N_L2
part E pins: A12 25P_L11, A13 25N_L11, A14 26P_L3, A15 26N_L3, A16 26P_L1, A17 26N_L1, B11 25P_L10, B12 25P_L12, B13 25N_L12, B14 26P_L2, B15 26N_L2, B16 26P_L4, B17 26N_L4, C11 25N_L10, C12 25P_L5, C13 25N_L5, C14 25P_L8, C15 25N_L8, C16 26P_L5, C17 26N_L5, C18 26P_L7, C19 26N_L7, D11 25P_L9, D12 25P_L4, D13 25N_L4, D14 25P_L6, D15 25N_L6, D16 26P_L6, D17 26N_L6, D18 26P_L8, D19 26N_L8, E11 25N_L9, E12 25P_L3, E13 25N_L3, E14 25P_L7, E15 25N_L7, E16 26P_L9, E17 26N_L9, E18 26P_L11, E19 26N_L11, F11 25P_L1, F12 25N_L1, F13 25P_L2, F14 25N_L2, F15 26P_L10, F16 26N_L10, F17 26P_L12, F18 26N_L12, G20 VCCO_HDIO_25, G21 VCCO_HDIO_26
part F pins: A5 65_T3, A6 65P_L19, B5 65_T2, B6 65N_L19, C5 65P_L21, C6 65P_L24, D5 65N_L21, D6 65N_L24, E5 65P_L14, E6 65P_L23, E8 65P_L20, F5 65N_L14, F6 65N_L23, F8 65N_L20, G3 65_T1, G5 65P_L13, G6 65P_L18, G15 VCCO_HPIO_65, H5 65N_L13, H6 65N_L18, H15 VREF_65, J4 65P_L10, J5 64_T0, J6 65P_L17, K4 65N_L10, K5 64_T3, K6 65N_L17, L1 65P_L8, L4 65P_L11, L5 65P_L6, L6 65P_L5, M1 65N_L8, M2 65P_L9, M4 65N_L11, M5 65N_L6, M6 65N_L5, N1 65P_L7, N2 65N_L9, N4 65P_L22, N5 65P_L4, N6 65P_L3, N14 VREF_64, P1 65N_L7, P2 65P_L12, P3 65_T0, P4 65N_L22, P5 65N_L4, P6 65N_L3, P14 VCCO_HPIO_64, R1 64P_L18, R2 65N_L12, R3 64_T2, R4 65P_L15, R5 65P_L2, R6 65P_L1, R7 64P_L6, R8 64P_L5, R9 64P_L3, R10 64P_L11, T1 64N_L18, T2 64P_L17, T4 65N_L15, T5 65N_L2, T6 65N_L1, T7 64N_L6, T8 64N_L5, T9 64N_L3, T10 64N_L11, U1 64P_L24, U2 64N_L17, U4 65P_L16, U5 64P_L14, U6 64P_L15, U7 64P_L13, U8 64P_L4, U9 64P_L1, U10 64P_L12, U11 64P_L2, V1 64N_L24, V2 64P_L16, V3 64_T1, V4 65N_L16, V5 64N_L14, V6 64N_L15, V7 64N_L13, V8 64N_L4, V9 64N_L1, V10 64N_L12, V11 64N_L2, W2 64N_L16, W3 64P_L23, W4 64P_L22, W5 64P_L21, W6 64P_L20, W7 64P_L19, W8 64P_L10, W9 64P_L8, W10 64P_L9, W11 64P_L7, Y3 64N_L23, Y4 64N_L22, Y5 64N_L21, Y6 64N_L20, Y7 64N_L19, Y8 64N_L10, Y9 64N_L8, Y10 64N_L9, Y11 64N_L7
part G pins: A3 66P_L10, A4 66P_L19, A7 66P_L21, A8 66P_L13, A9 66P_L23, A10 66P_L18, B2 66P_L9, B3 66N_L10, B4 66N_L19, B7 66N_L21, B8 66N_L13, B9 66N_L23, B10 66N_L18, C1 66P_L8, C2 66N_L9, C3 66_T1, C4 66P_L11, C7 66_T3, C8 66P_L15, C9 66P_L24, C10 66P_L17, D1 66N_L8, D2 66P_L12, D4 66N_L11, D7 66_T2, D8 66N_L15, D9 66N_L24, D10 66N_L17, E1 66P_L7, E2 66N_L12, E4 66P_L14, E7 66P_L20, E9 66P_L22, E10 66P_L16, F1 66N_L7, F2 66P_L5, F3 66_T0, F4 66N_L14, F7 66N_L20, F9 66N_L22, F10 66N_L16, G1 66P_L2, G2 66N_L5, G4 66P_L6, G16 VCCO_HPIO_66, H1 66N_L2, H2 66P_L4, H4 66N_L6, H16 VREF_66, J1 66P_L1, J2 66N_L4, K1 66N_L1, K2 66P_L3, L2 66N_L3
part H pins: J25 VCCO_PSIO_501, P23 VCCO_PSIO_500, R19 MIO30, R20 MIO31, R21 MIO35, R22 MIO38, R23 MIO39, R24 MIO41, T19 MIO29, T20 MIO27, T21 MIO32, T22 MIO37, T23 MIO36, T24 MIO40, T25 MIO44, T26 MIO46, T27 MIO45, T28 MIO48, U20 MIO28, U21 MIO26, U22 MIO33, U23 MIO34, U24 MIO42, U25 MIO43, U26 MIO47, U27 MIO51, U28 MIO49, U29 MIO50, U30 MIO25, V20 MIO2, V21 MIO6, V22 MIO8, V23 MIO9, V24 MIO11, V25 MIO23, V26 MIO24, V27 MIO20, V28 MIO18, V29 MIO22, V30 MIO21, W20 MIO0, W21 MIO1, W22 MIO7, W23 MIO5, W24 MIO15, W25 MIO12, W26 MIO17, Y20 MIO3, Y21 MIO4, Y22 MIO13, Y23 MIO14, Y24 MIO16, Y25 MIO10, Y26 MIO19
part I pins: A24 MIO65, A25 MIO75, B24 MIO67, C24 MIO70, C25 MIO71, D20 MIO57, D23 MIO62, D24 MIO68, E20 MIO55, E21 MIO59, E22 MIO60, E23 MIO69, E24 MIO74, E25 MIO76, F19 MIO56, F20 MIO53, F21 MIO54, F22 MIO61, F23 MIO63, F24 MIO64, G25 VCCO_PSIO_502, L25 MIO58, N25 MIO77, P25 MIO52, P26 MIO72, R25 MIO66, R26 MIO73
part J pins: A27 GTRX_TX_P3, A28 GTRX_TX_N3, B29 GTRX_CLK_P3, B30 GTRX_CLK_N3, C27 GTRX_RX_P3, C28 GTRX_RX_N3, D29 GTRX_RX_P2, D30 GTRX_RX_N2, E27 GTRX_CLK_P2, E28 GTRX_CLK_N2, F29 GTRX_TX_P2, F30 GTRX_TX_N2, G27 GTRX_TX_P1, G28 GTRX_TX_N1, H26 PS_MGTRREF, H29 GTRX_CLK_P1, H30 GTRX_CLK_N1, J27 GTRX_RX_P1, J28 GTRX_RX_N1, K29 GTRX_RX_P0, K30 GTRX_RX_N0, L27 GTRX_CLK_P0, L28 GTRX_CLK_N0, M29 GTRX_TX_P0, M30 GTRX_TX_N0
part K pins: A1 VSS, A26 VSS, A29 VSS, A30 VSS, B1 VSS, B25 VSS, B27 VSS, B28 VSS, C26 VSS, C29 VSS, C30 VSS, D25 VSS, D27 VSS, D28 VSS, E26 VSS, E29 VSS, E30 VSS, F27 VSS, F28 VSS, G7 VSS, G8 VSS, G9 VSS, G10 VSS, G11 VSS, G12 VSS, G13 VSS, G17 VSS, G18 VSS, G19 VSS, G26 VSS, G29 VSS, G30 VSS, H7 VSS, H10 VSS, H11 VSS, H12 VSS, H13 VSS, H14 VSS, H17 VSS, H18 VSS, H19 VSS, H20 VSS, H21 VSS, H25 VSS, H27 VSS, H28 VSS, J7 VSS, J11 VSS, J12 VSS, J13 VSS, J14 VSS, J15 VSS, J16 VSS, J17 VSS, J18 VSS, J20 VSS, J21 VSS, J26 VSS, J29 VSS, J30 VSS, K7 VSS, K11 VSS, K12 VSS, K13 VSS, K14 VSS, K15 VSS, K16 VSS, K17 VSS, K18 VSS, K20 VSS, K21 VSS, K22 VSS, K23 VSS, K24 VSS, K25 VSS, K27 VSS, K28 VSS, L7 VSS, L12 VSS, L14 VSS, L15 VSS, L16 VSS, L18 VSS, L20 VSS, L22 VSS, L23 VSS, L24 VSS, L26 VSS, L29 VSS, L30 VSS, M7 VSS, M12 VSS, M14 VSS, M15 VSS, M18 VSS, M19 VSS, M20 VSS, M23 VSS, M24 VSS, M25 VSS, M27 VSS, M28 VSS, N7 VSS, N11 VSS, N12 VSS, N13 VSS, N15 VSS, N16 VSS, N17 VSS, N21 VSS, N22 VSS, N26 VSS, N29 VSS, N30 VSS, P7 VSS, P8 VSS, P9 VSS, P10 VSS, P11 VSS, P12 VSS, P13 VSS, W1 VSS, W28 VSS, W29 VSS, W30 VSS, Y1 VSS, Y28 VSS
part L pins: A11 RSVD, E3 RSVD, K26 +MGTRAVCC, L17 VCC_PSPLL, L19 RSVD, L21 VCCO_PSDDR, M16 RSVD, M17 RSVD, M21 RSVD, M22 RSVD, M26 +MGTRAVTT, N18 RSVD, N19 RSVD, N20 RSVD, P16 RSVD, P17 RSVD, P21 RSVD, P22 RSVD, W27 RSVD, Y27 RSVD

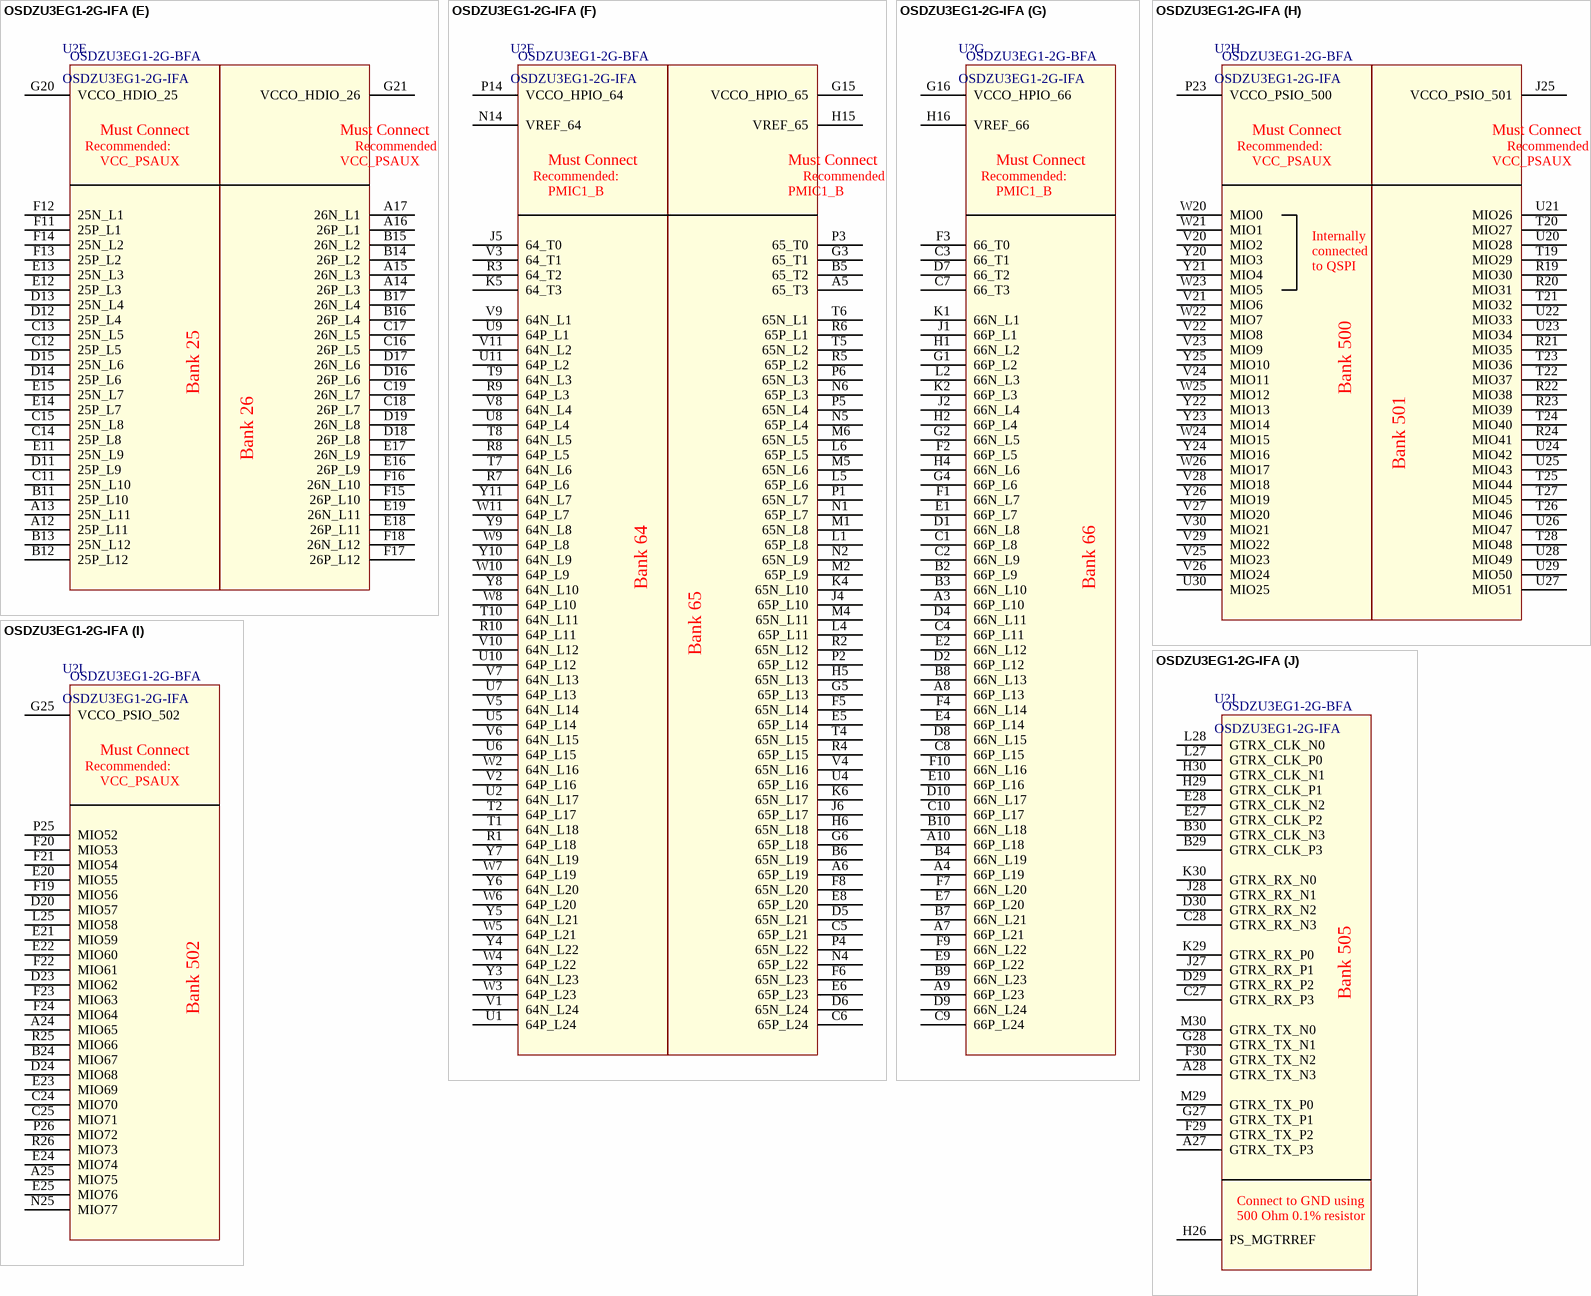
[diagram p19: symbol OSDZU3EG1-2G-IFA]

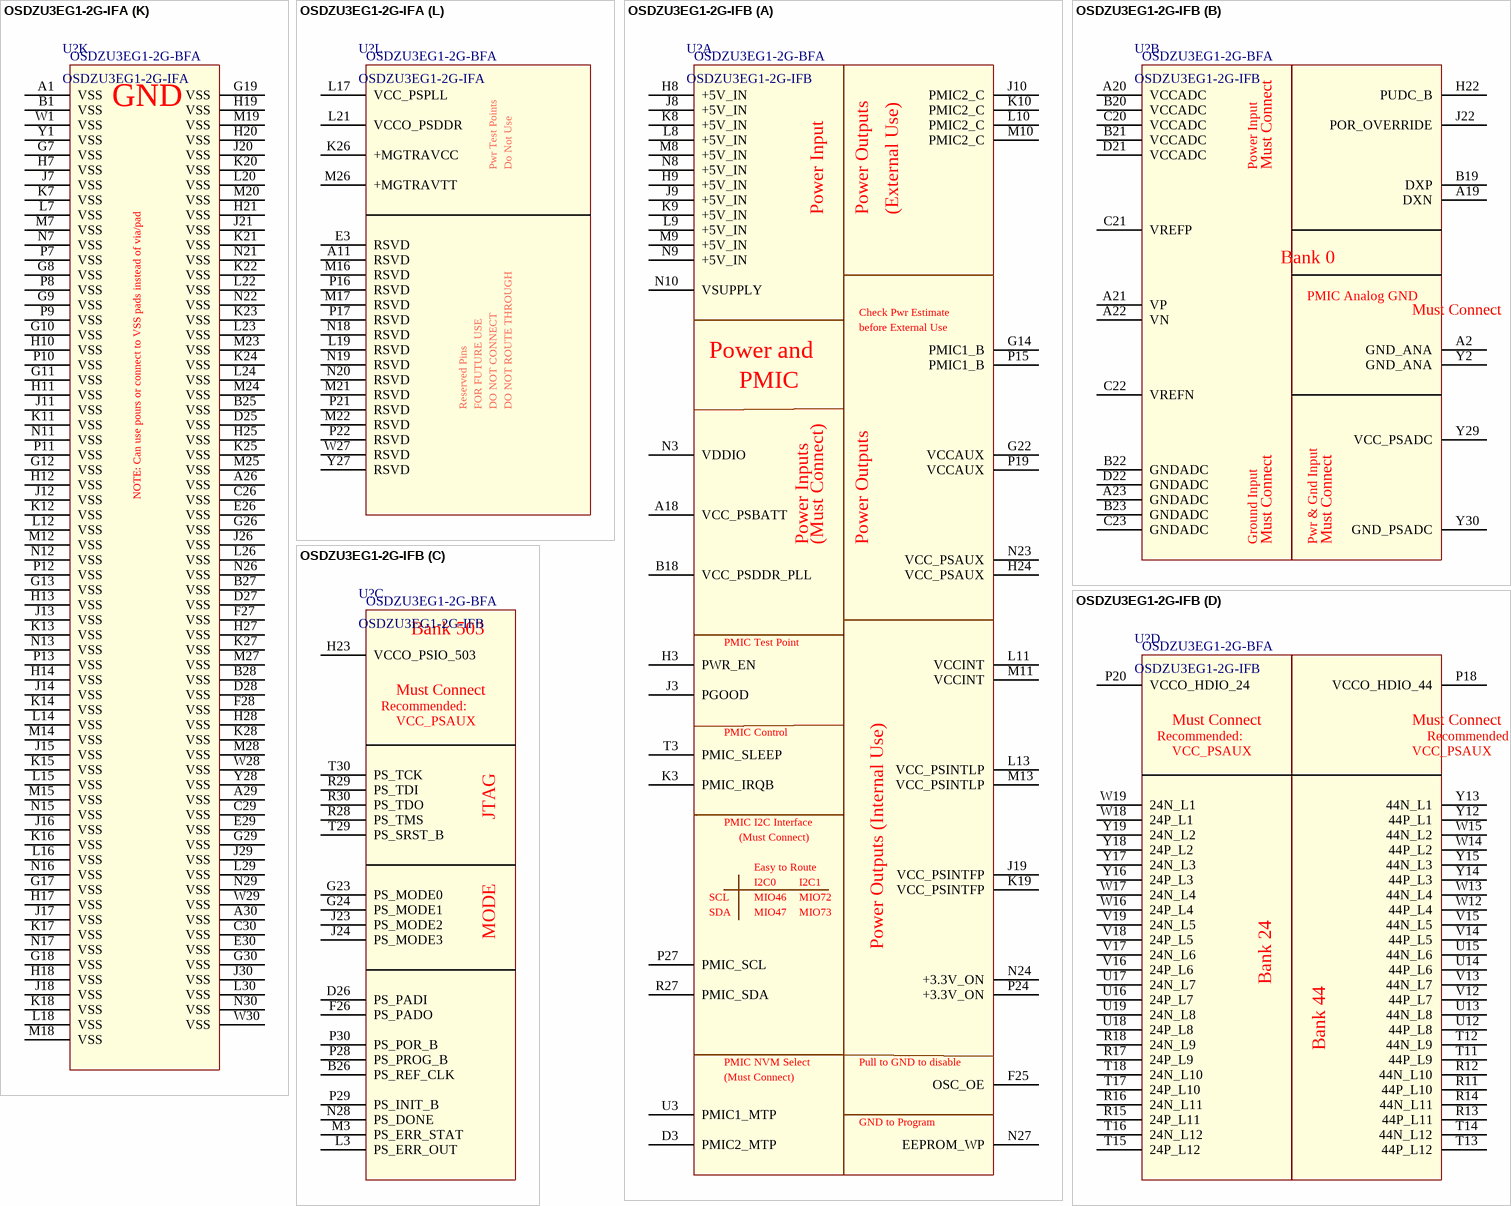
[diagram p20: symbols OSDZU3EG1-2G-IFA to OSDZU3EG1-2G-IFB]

## OSDZU3EG1-2G-IFA
designator U?  PartNumber: OSDZU3EG1-2G-BFA
Octavo Systems LLC OSDZU3x Family SiP; 20.5mm x 40mm, 1mm pitch 600 pin BGA contains Xilinx XCZU3EG1, 2GB DDR4, two IRPS5401, 32MB QSPI NOR Flash (3.3V), MEMS Oscillator, RTC Crystal and passives; Industrial Temperature (case):  -40C to 85C.
footprint BGA_20x30_600_1p00mm (600 pin 1mm pitch footprint)
part A pins: A18 VCC_PSBATT, B18 VCC_PSDDR_PLL, D3 PMIC2_MTP, F25 OSC_OE, G14 PMIC1_B, G22 VCCAUX, H3 PWR_EN, H8 +5V_IN, H9 +5V_IN, H24 VCC_PSAUX, J3 PGOOD, J8 +5V_IN, J9 +5V_IN, J10 PMIC2_C, J19 VCC_PSINTFP, K3 PMIC_IRQB, K8 +5V_IN, K9 +5V_IN, K10 PMIC2_C, K19 VCC_PSINTFP, L8 +5V_IN, L9 +5V_IN, L10 PMIC2_C, L11 VCCINT, L13 VCC_PSINTLP, M8 +5V_IN, M9 +5V_IN, M10 PMIC2_C, M11 VCCINT, M13 VCC_PSINTLP, N3 VDDIO, N8 +5V_IN, N9 +5V_IN, N10 VSUPPLY, N23 VCC_PSAUX, N24 +3.3V_ON, N27 EEPROM_WP, P15 PMIC1_B, P19 VCCAUX, P24 +3.3V_ON, P27 PMIC_SCL, R27 PMIC_SDA, T3 PMIC_SLEEP, U3 PMIC1_MTP
part B pins: A2 GND_ANA, A19 DXN, A20 VCCADC, A21 VP, A22 VN, A23 GNDADC, B19 DXP, B20 VCCADC, B21 VCCADC, B22 GNDADC, B23 GNDADC, C20 VCCADC, C21 VREFP, C22 VREFN, C23 GNDADC, D21 VCCADC, D22 GNDADC, H22 PUDC_B, J22 POR_OVERRIDE, Y2 GND_ANA, Y29 VCC_PSADC, Y30 GND_PSADC
part C pins: B26 PS_REF_CLK, D26 PS_PADI, F26 PS_PADO, G23 PS_MODE0, G24 PS_MODE1, H23 VCCO_PSIO_503, J23 PS_MODE2, J24 PS_MODE3, L3 PS_ERR_OUT, M3 PS_ERR_STAT, N28 PS_DONE, P28 PS_PROG_B, P29 PS_INIT_B, P30 PS_POR_B, R28 PS_TMS, R29 PS_TDI, R30 PS_TDO, T29 PS_SRST_B, T30 PS_TCK
part D pins: P18 VCCO_HDIO_44, P20 VCCO_HDIO_24, R11 44P_L10, R12 44N_L10, R13 44P_L11, R14 44N_L11, R15 24P_L11, R16 24N_L11, R17 24P_L9, R18 24N_L9, T11 44P_L9, T12 44N_L9, T13 44P_L12, T14 44N_L12, T15 24P_L12, T16 24N_L12, T17 24P_L10, T18 24N_L10, U12 44P_L8, U13 44N_L8, U14 44P_L6, U15 44N_L6, U16 24P_L7, U17 24N_L7, U18 24P_L8, U19 24N_L8, V12 44P_L7, V13 44N_L7, V14 44P_L5, V15 44N_L5, V16 24P_L6, V17 24N_L6, V18 24P_L5, V19 24N_L5, W12 44P_L4, W13 44N_L4, W14 44P_L2, W15 44N_L2, W16 24P_L4, W17 24N_L4, W18 24P_L1, W19 24N_L1, Y12 44P_L1, Y13 44N_L1, Y14 44P_L3, Y15 44N_L3, Y16 24P_L3, Y17 24N_L3, Y18 24P_L2, Y19 24N_L2
part E pins: A12 25P_L11, A13 25N_L11, A14 26P_L3, A15 26N_L3, A16 26P_L1, A17 26N_L1, B11 25P_L10, B12 25P_L12, B13 25N_L12, B14 26P_L2, B15 26N_L2, B16 26P_L4, B17 26N_L4, C11 25N_L10, C12 25P_L5, C13 25N_L5, C14 25P_L8, C15 25N_L8, C16 26P_L5, C17 26N_L5, C18 26P_L7, C19 26N_L7, D11 25P_L9, D12 25P_L4, D13 25N_L4, D14 25P_L6, D15 25N_L6, D16 26P_L6, D17 26N_L6, D18 26P_L8, D19 26N_L8, E11 25N_L9, E12 25P_L3, E13 25N_L3, E14 25P_L7, E15 25N_L7, E16 26P_L9, E17 26N_L9, E18 26P_L11, E19 26N_L11, F11 25P_L1, F12 25N_L1, F13 25P_L2, F14 25N_L2, F15 26P_L10, F16 26N_L10, F17 26P_L12, F18 26N_L12, G20 VCCO_HDIO_25, G21 VCCO_HDIO_26
part F pins: A5 65_T3, A6 65P_L19, B5 65_T2, B6 65N_L19, C5 65P_L21, C6 65P_L24, D5 65N_L21, D6 65N_L24, E5 65P_L14, E6 65P_L23, E8 65P_L20, F5 65N_L14, F6 65N_L23, F8 65N_L20, G3 65_T1, G5 65P_L13, G6 65P_L18, G15 VCCO_HPIO_65, H5 65N_L13, H6 65N_L18, H15 VREF_65, J4 65P_L10, J5 64_T0, J6 65P_L17, K4 65N_L10, K5 64_T3, K6 65N_L17, L1 65P_L8, L4 65P_L11, L5 65P_L6, L6 65P_L5, M1 65N_L8, M2 65P_L9, M4 65N_L11, M5 65N_L6, M6 65N_L5, N1 65P_L7, N2 65N_L9, N4 65P_L22, N5 65P_L4, N6 65P_L3, N14 VREF_64, P1 65N_L7, P2 65P_L12, P3 65_T0, P4 65N_L22, P5 65N_L4, P6 65N_L3, P14 VCCO_HPIO_64, R1 64P_L18, R2 65N_L12, R3 64_T2, R4 65P_L15, R5 65P_L2, R6 65P_L1, R7 64P_L6, R8 64P_L5, R9 64P_L3, R10 64P_L11, T1 64N_L18, T2 64P_L17, T4 65N_L15, T5 65N_L2, T6 65N_L1, T7 64N_L6, T8 64N_L5, T9 64N_L3, T10 64N_L11, U1 64P_L24, U2 64N_L17, U4 65P_L16, U5 64P_L14, U6 64P_L15, U7 64P_L13, U8 64P_L4, U9 64P_L1, U10 64P_L12, U11 64P_L2, V1 64N_L24, V2 64P_L16, V3 64_T1, V4 65N_L16, V5 64N_L14, V6 64N_L15, V7 64N_L13, V8 64N_L4, V9 64N_L1, V10 64N_L12, V11 64N_L2, W2 64N_L16, W3 64P_L23, W4 64P_L22, W5 64P_L21, W6 64P_L20, W7 64P_L19, W8 64P_L10, W9 64P_L8, W10 64P_L9, W11 64P_L7, Y3 64N_L23, Y4 64N_L22, Y5 64N_L21, Y6 64N_L20, Y7 64N_L19, Y8 64N_L10, Y9 64N_L8, Y10 64N_L9, Y11 64N_L7
part G pins: A3 66P_L10, A4 66P_L19, A7 66P_L21, A8 66P_L13, A9 66P_L23, A10 66P_L18, B2 66P_L9, B3 66N_L10, B4 66N_L19, B7 66N_L21, B8 66N_L13, B9 66N_L23, B10 66N_L18, C1 66P_L8, C2 66N_L9, C3 66_T1, C4 66P_L11, C7 66_T3, C8 66P_L15, C9 66P_L24, C10 66P_L17, D1 66N_L8, D2 66P_L12, D4 66N_L11, D7 66_T2, D8 66N_L15, D9 66N_L24, D10 66N_L17, E1 66P_L7, E2 66N_L12, E4 66P_L14, E7 66P_L20, E9 66P_L22, E10 66P_L16, F1 66N_L7, F2 66P_L5, F3 66_T0, F4 66N_L14, F7 66N_L20, F9 66N_L22, F10 66N_L16, G1 66P_L2, G2 66N_L5, G4 66P_L6, G16 VCCO_HPIO_66, H1 66N_L2, H2 66P_L4, H4 66N_L6, H16 VREF_66, J1 66P_L1, J2 66N_L4, K1 66N_L1, K2 66P_L3, L2 66N_L3
part H pins: J25 VCCO_PSIO_501, P23 VCCO_PSIO_500, R19 MIO30, R20 MIO31, R21 MIO35, R22 MIO38, R23 MIO39, R24 MIO41, T19 MIO29, T20 MIO27, T21 MIO32, T22 MIO37, T23 MIO36, T24 MIO40, T25 MIO44, T26 MIO46, T27 MIO45, T28 MIO48, U20 MIO28, U21 MIO26, U22 MIO33, U23 MIO34, U24 MIO42, U25 MIO43, U26 MIO47, U27 MIO51, U28 MIO49, U29 MIO50, U30 MIO25, V20 MIO2, V21 MIO6, V22 MIO8, V23 MIO9, V24 MIO11, V25 MIO23, V26 MIO24, V27 MIO20, V28 MIO18, V29 MIO22, V30 MIO21, W20 MIO0, W21 MIO1, W22 MIO7, W23 MIO5, W24 MIO15, W25 MIO12, W26 MIO17, Y20 MIO3, Y21 MIO4, Y22 MIO13, Y23 MIO14, Y24 MIO16, Y25 MIO10, Y26 MIO19
part I pins: A24 MIO65, A25 MIO75, B24 MIO67, C24 MIO70, C25 MIO71, D20 MIO57, D23 MIO62, D24 MIO68, E20 MIO55, E21 MIO59, E22 MIO60, E23 MIO69, E24 MIO74, E25 MIO76, F19 MIO56, F20 MIO53, F21 MIO54, F22 MIO61, F23 MIO63, F24 MIO64, G25 VCCO_PSIO_502, L25 MIO58, N25 MIO77, P25 MIO52, P26 MIO72, R25 MIO66, R26 MIO73
part J pins: A27 GTRX_TX_P3, A28 GTRX_TX_N3, B29 GTRX_CLK_P3, B30 GTRX_CLK_N3, C27 GTRX_RX_P3, C28 GTRX_RX_N3, D29 GTRX_RX_P2, D30 GTRX_RX_N2, E27 GTRX_CLK_P2, E28 GTRX_CLK_N2, F29 GTRX_TX_P2, F30 GTRX_TX_N2, G27 GTRX_TX_P1, G28 GTRX_TX_N1, H26 PS_MGTRREF, H29 GTRX_CLK_P1, H30 GTRX_CLK_N1, J27 GTRX_RX_P1, J28 GTRX_RX_N1, K29 GTRX_RX_P0, K30 GTRX_RX_N0, L27 GTRX_CLK_P0, L28 GTRX_CLK_N0, M29 GTRX_TX_P0, M30 GTRX_TX_N0
part K pins: A1 VSS, A26 VSS, A29 VSS, A30 VSS, B1 VSS, B25 VSS, B27 VSS, B28 VSS, C26 VSS, C29 VSS, C30 VSS, D25 VSS, D27 VSS, D28 VSS, E26 VSS, E29 VSS, E30 VSS, F27 VSS, F28 VSS, G7 VSS, G8 VSS, G9 VSS, G10 VSS, G11 VSS, G12 VSS, G13 VSS, G17 VSS, G18 VSS, G19 VSS, G26 VSS, G29 VSS, G30 VSS, H7 VSS, H10 VSS, H11 VSS, H12 VSS, H13 VSS, H14 VSS, H17 VSS, H18 VSS, H19 VSS, H20 VSS, H21 VSS, H25 VSS, H27 VSS, H28 VSS, J7 VSS, J11 VSS, J12 VSS, J13 VSS, J14 VSS, J15 VSS, J16 VSS, J17 VSS, J18 VSS, J20 VSS, J21 VSS, J26 VSS, J29 VSS, J30 VSS, K7 VSS, K11 VSS, K12 VSS, K13 VSS, K14 VSS, K15 VSS, K16 VSS, K17 VSS, K18 VSS, K20 VSS, K21 VSS, K22 VSS, K23 VSS, K24 VSS, K25 VSS, K27 VSS, K28 VSS, L7 VSS, L12 VSS, L14 VSS, L15 VSS, L16 VSS, L18 VSS, L20 VSS, L22 VSS, L23 VSS, L24 VSS, L26 VSS, L29 VSS, L30 VSS, M7 VSS, M12 VSS, M14 VSS, M15 VSS, M18 VSS, M19 VSS, M20 VSS, M23 VSS, M24 VSS, M25 VSS, M27 VSS, M28 VSS, N7 VSS, N11 VSS, N12 VSS, N13 VSS, N15 VSS, N16 VSS, N17 VSS, N21 VSS, N22 VSS, N26 VSS, N29 VSS, N30 VSS, P7 VSS, P8 VSS, P9 VSS, P10 VSS, P11 VSS, P12 VSS, P13 VSS, W1 VSS, W28 VSS, W29 VSS, W30 VSS, Y1 VSS, Y28 VSS
part L pins: A11 RSVD, E3 RSVD, K26 +MGTRAVCC, L17 VCC_PSPLL, L19 RSVD, L21 VCCO_PSDDR, M16 RSVD, M17 RSVD, M21 RSVD, M22 RSVD, M26 +MGTRAVTT, N18 RSVD, N19 RSVD, N20 RSVD, P16 RSVD, P17 RSVD, P21 RSVD, P22 RSVD, W27 RSVD, Y27 RSVD

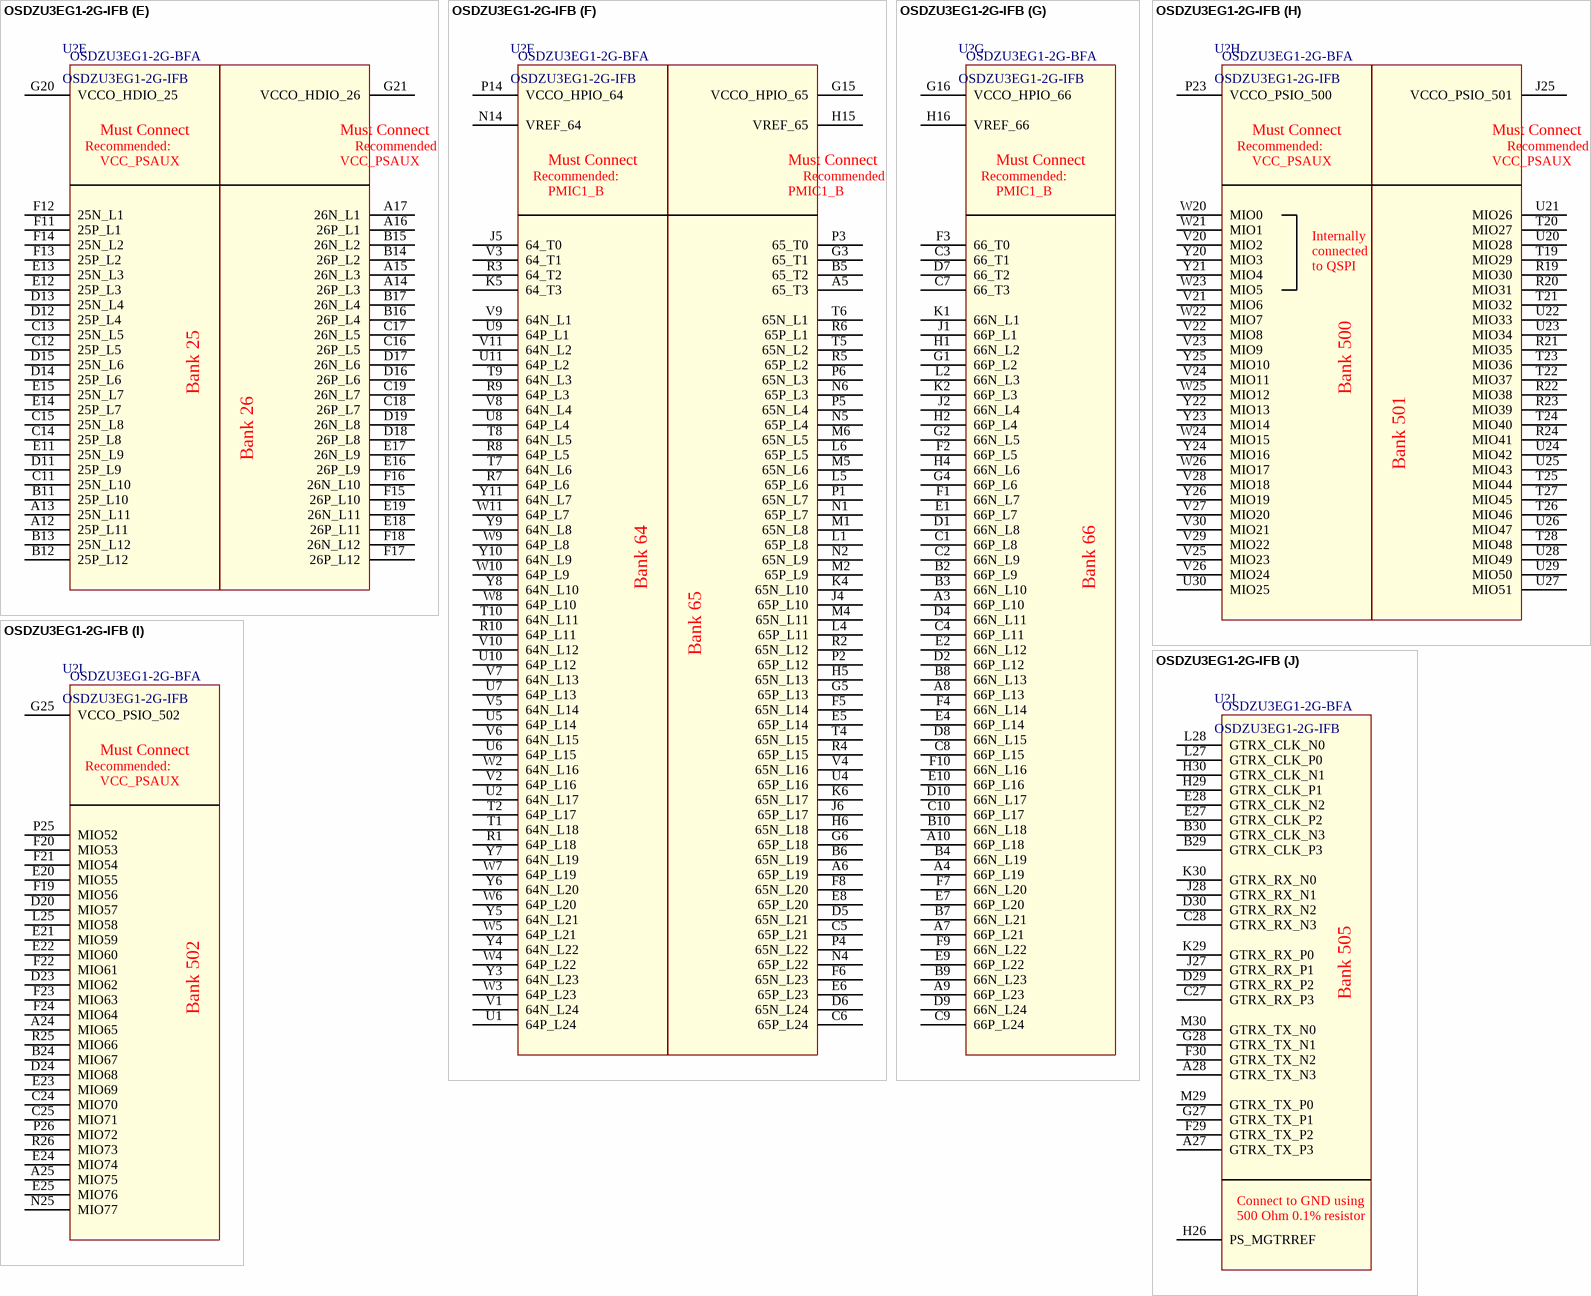
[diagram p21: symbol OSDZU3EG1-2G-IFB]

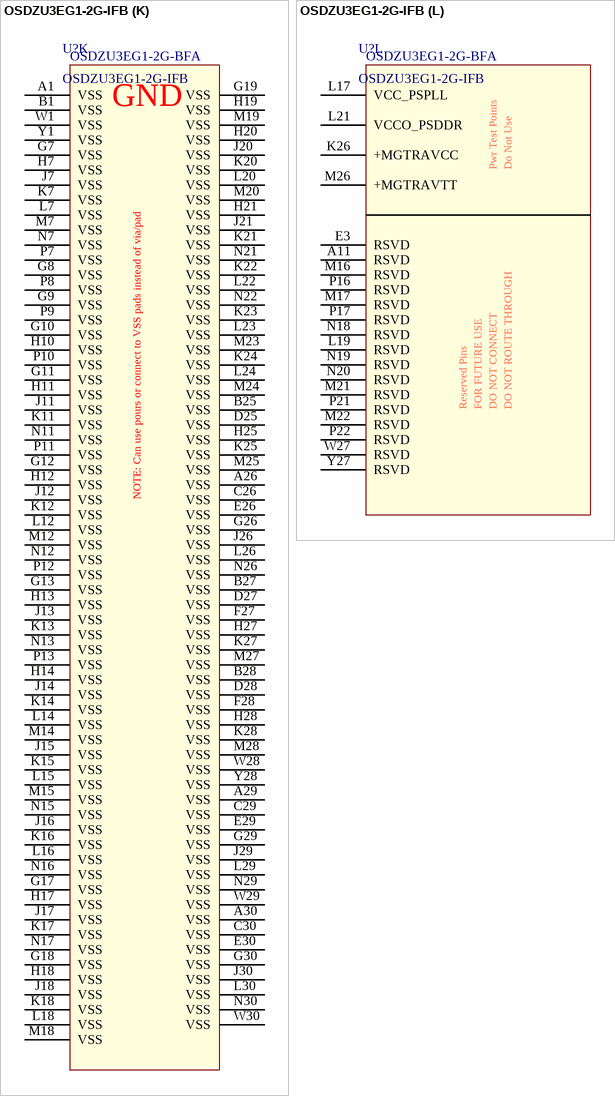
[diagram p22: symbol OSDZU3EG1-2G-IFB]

## OSDZU3EG1-2G-IFB
designator U?  PartNumber: OSDZU3EG1-2G-BFA
Octavo Systems LLC OSDZU3x Family SiP; 20.5mm x 40mm, 1mm pitch 600 pin BGA contains Xilinx XCZU3EG1, 2GB DDR4, two IRPS5401, 32MB QSPI NOR Flash (1.8V), MEMS Oscillator, RTC Crystal and passives; Industrial Temperature (case):  -40C to 85C.
footprint BGA_20x30_600_1p00mm (600 pin 1mm pitch footprint)
part A pins: A18 VCC_PSBATT, B18 VCC_PSDDR_PLL, D3 PMIC2_MTP, F25 OSC_OE, G14 PMIC1_B, G22 VCCAUX, H3 PWR_EN, H8 +5V_IN, H9 +5V_IN, H24 VCC_PSAUX, J3 PGOOD, J8 +5V_IN, J9 +5V_IN, J10 PMIC2_C, J19 VCC_PSINTFP, K3 PMIC_IRQB, K8 +5V_IN, K9 +5V_IN, K10 PMIC2_C, K19 VCC_PSINTFP, L8 +5V_IN, L9 +5V_IN, L10 PMIC2_C, L11 VCCINT, L13 VCC_PSINTLP, M8 +5V_IN, M9 +5V_IN, M10 PMIC2_C, M11 VCCINT, M13 VCC_PSINTLP, N3 VDDIO, N8 +5V_IN, N9 +5V_IN, N10 VSUPPLY, N23 VCC_PSAUX, N24 +3.3V_ON, N27 EEPROM_WP, P15 PMIC1_B, P19 VCCAUX, P24 +3.3V_ON, P27 PMIC_SCL, R27 PMIC_SDA, T3 PMIC_SLEEP, U3 PMIC1_MTP
part B pins: A2 GND_ANA, A19 DXN, A20 VCCADC, A21 VP, A22 VN, A23 GNDADC, B19 DXP, B20 VCCADC, B21 VCCADC, B22 GNDADC, B23 GNDADC, C20 VCCADC, C21 VREFP, C22 VREFN, C23 GNDADC, D21 VCCADC, D22 GNDADC, H22 PUDC_B, J22 POR_OVERRIDE, Y2 GND_ANA, Y29 VCC_PSADC, Y30 GND_PSADC
part C pins: B26 PS_REF_CLK, D26 PS_PADI, F26 PS_PADO, G23 PS_MODE0, G24 PS_MODE1, H23 VCCO_PSIO_503, J23 PS_MODE2, J24 PS_MODE3, L3 PS_ERR_OUT, M3 PS_ERR_STAT, N28 PS_DONE, P28 PS_PROG_B, P29 PS_INIT_B, P30 PS_POR_B, R28 PS_TMS, R29 PS_TDI, R30 PS_TDO, T29 PS_SRST_B, T30 PS_TCK
part D pins: P18 VCCO_HDIO_44, P20 VCCO_HDIO_24, R11 44P_L10, R12 44N_L10, R13 44P_L11, R14 44N_L11, R15 24P_L11, R16 24N_L11, R17 24P_L9, R18 24N_L9, T11 44P_L9, T12 44N_L9, T13 44P_L12, T14 44N_L12, T15 24P_L12, T16 24N_L12, T17 24P_L10, T18 24N_L10, U12 44P_L8, U13 44N_L8, U14 44P_L6, U15 44N_L6, U16 24P_L7, U17 24N_L7, U18 24P_L8, U19 24N_L8, V12 44P_L7, V13 44N_L7, V14 44P_L5, V15 44N_L5, V16 24P_L6, V17 24N_L6, V18 24P_L5, V19 24N_L5, W12 44P_L4, W13 44N_L4, W14 44P_L2, W15 44N_L2, W16 24P_L4, W17 24N_L4, W18 24P_L1, W19 24N_L1, Y12 44P_L1, Y13 44N_L1, Y14 44P_L3, Y15 44N_L3, Y16 24P_L3, Y17 24N_L3, Y18 24P_L2, Y19 24N_L2
part E pins: A12 25P_L11, A13 25N_L11, A14 26P_L3, A15 26N_L3, A16 26P_L1, A17 26N_L1, B11 25P_L10, B12 25P_L12, B13 25N_L12, B14 26P_L2, B15 26N_L2, B16 26P_L4, B17 26N_L4, C11 25N_L10, C12 25P_L5, C13 25N_L5, C14 25P_L8, C15 25N_L8, C16 26P_L5, C17 26N_L5, C18 26P_L7, C19 26N_L7, D11 25P_L9, D12 25P_L4, D13 25N_L4, D14 25P_L6, D15 25N_L6, D16 26P_L6, D17 26N_L6, D18 26P_L8, D19 26N_L8, E11 25N_L9, E12 25P_L3, E13 25N_L3, E14 25P_L7, E15 25N_L7, E16 26P_L9, E17 26N_L9, E18 26P_L11, E19 26N_L11, F11 25P_L1, F12 25N_L1, F13 25P_L2, F14 25N_L2, F15 26P_L10, F16 26N_L10, F17 26P_L12, F18 26N_L12, G20 VCCO_HDIO_25, G21 VCCO_HDIO_26
part F pins: A5 65_T3, A6 65P_L19, B5 65_T2, B6 65N_L19, C5 65P_L21, C6 65P_L24, D5 65N_L21, D6 65N_L24, E5 65P_L14, E6 65P_L23, E8 65P_L20, F5 65N_L14, F6 65N_L23, F8 65N_L20, G3 65_T1, G5 65P_L13, G6 65P_L18, G15 VCCO_HPIO_65, H5 65N_L13, H6 65N_L18, H15 VREF_65, J4 65P_L10, J5 64_T0, J6 65P_L17, K4 65N_L10, K5 64_T3, K6 65N_L17, L1 65P_L8, L4 65P_L11, L5 65P_L6, L6 65P_L5, M1 65N_L8, M2 65P_L9, M4 65N_L11, M5 65N_L6, M6 65N_L5, N1 65P_L7, N2 65N_L9, N4 65P_L22, N5 65P_L4, N6 65P_L3, N14 VREF_64, P1 65N_L7, P2 65P_L12, P3 65_T0, P4 65N_L22, P5 65N_L4, P6 65N_L3, P14 VCCO_HPIO_64, R1 64P_L18, R2 65N_L12, R3 64_T2, R4 65P_L15, R5 65P_L2, R6 65P_L1, R7 64P_L6, R8 64P_L5, R9 64P_L3, R10 64P_L11, T1 64N_L18, T2 64P_L17, T4 65N_L15, T5 65N_L2, T6 65N_L1, T7 64N_L6, T8 64N_L5, T9 64N_L3, T10 64N_L11, U1 64P_L24, U2 64N_L17, U4 65P_L16, U5 64P_L14, U6 64P_L15, U7 64P_L13, U8 64P_L4, U9 64P_L1, U10 64P_L12, U11 64P_L2, V1 64N_L24, V2 64P_L16, V3 64_T1, V4 65N_L16, V5 64N_L14, V6 64N_L15, V7 64N_L13, V8 64N_L4, V9 64N_L1, V10 64N_L12, V11 64N_L2, W2 64N_L16, W3 64P_L23, W4 64P_L22, W5 64P_L21, W6 64P_L20, W7 64P_L19, W8 64P_L10, W9 64P_L8, W10 64P_L9, W11 64P_L7, Y3 64N_L23, Y4 64N_L22, Y5 64N_L21, Y6 64N_L20, Y7 64N_L19, Y8 64N_L10, Y9 64N_L8, Y10 64N_L9, Y11 64N_L7
part G pins: A3 66P_L10, A4 66P_L19, A7 66P_L21, A8 66P_L13, A9 66P_L23, A10 66P_L18, B2 66P_L9, B3 66N_L10, B4 66N_L19, B7 66N_L21, B8 66N_L13, B9 66N_L23, B10 66N_L18, C1 66P_L8, C2 66N_L9, C3 66_T1, C4 66P_L11, C7 66_T3, C8 66P_L15, C9 66P_L24, C10 66P_L17, D1 66N_L8, D2 66P_L12, D4 66N_L11, D7 66_T2, D8 66N_L15, D9 66N_L24, D10 66N_L17, E1 66P_L7, E2 66N_L12, E4 66P_L14, E7 66P_L20, E9 66P_L22, E10 66P_L16, F1 66N_L7, F2 66P_L5, F3 66_T0, F4 66N_L14, F7 66N_L20, F9 66N_L22, F10 66N_L16, G1 66P_L2, G2 66N_L5, G4 66P_L6, G16 VCCO_HPIO_66, H1 66N_L2, H2 66P_L4, H4 66N_L6, H16 VREF_66, J1 66P_L1, J2 66N_L4, K1 66N_L1, K2 66P_L3, L2 66N_L3
part H pins: J25 VCCO_PSIO_501, P23 VCCO_PSIO_500, R19 MIO30, R20 MIO31, R21 MIO35, R22 MIO38, R23 MIO39, R24 MIO41, T19 MIO29, T20 MIO27, T21 MIO32, T22 MIO37, T23 MIO36, T24 MIO40, T25 MIO44, T26 MIO46, T27 MIO45, T28 MIO48, U20 MIO28, U21 MIO26, U22 MIO33, U23 MIO34, U24 MIO42, U25 MIO43, U26 MIO47, U27 MIO51, U28 MIO49, U29 MIO50, U30 MIO25, V20 MIO2, V21 MIO6, V22 MIO8, V23 MIO9, V24 MIO11, V25 MIO23, V26 MIO24, V27 MIO20, V28 MIO18, V29 MIO22, V30 MIO21, W20 MIO0, W21 MIO1, W22 MIO7, W23 MIO5, W24 MIO15, W25 MIO12, W26 MIO17, Y20 MIO3, Y21 MIO4, Y22 MIO13, Y23 MIO14, Y24 MIO16, Y25 MIO10, Y26 MIO19
part I pins: A24 MIO65, A25 MIO75, B24 MIO67, C24 MIO70, C25 MIO71, D20 MIO57, D23 MIO62, D24 MIO68, E20 MIO55, E21 MIO59, E22 MIO60, E23 MIO69, E24 MIO74, E25 MIO76, F19 MIO56, F20 MIO53, F21 MIO54, F22 MIO61, F23 MIO63, F24 MIO64, G25 VCCO_PSIO_502, L25 MIO58, N25 MIO77, P25 MIO52, P26 MIO72, R25 MIO66, R26 MIO73
part J pins: A27 GTRX_TX_P3, A28 GTRX_TX_N3, B29 GTRX_CLK_P3, B30 GTRX_CLK_N3, C27 GTRX_RX_P3, C28 GTRX_RX_N3, D29 GTRX_RX_P2, D30 GTRX_RX_N2, E27 GTRX_CLK_P2, E28 GTRX_CLK_N2, F29 GTRX_TX_P2, F30 GTRX_TX_N2, G27 GTRX_TX_P1, G28 GTRX_TX_N1, H26 PS_MGTRREF, H29 GTRX_CLK_P1, H30 GTRX_CLK_N1, J27 GTRX_RX_P1, J28 GTRX_RX_N1, K29 GTRX_RX_P0, K30 GTRX_RX_N0, L27 GTRX_CLK_P0, L28 GTRX_CLK_N0, M29 GTRX_TX_P0, M30 GTRX_TX_N0
part K pins: A1 VSS, A26 VSS, A29 VSS, A30 VSS, B1 VSS, B25 VSS, B27 VSS, B28 VSS, C26 VSS, C29 VSS, C30 VSS, D25 VSS, D27 VSS, D28 VSS, E26 VSS, E29 VSS, E30 VSS, F27 VSS, F28 VSS, G7 VSS, G8 VSS, G9 VSS, G10 VSS, G11 VSS, G12 VSS, G13 VSS, G17 VSS, G18 VSS, G19 VSS, G26 VSS, G29 VSS, G30 VSS, H7 VSS, H10 VSS, H11 VSS, H12 VSS, H13 VSS, H14 VSS, H17 VSS, H18 VSS, H19 VSS, H20 VSS, H21 VSS, H25 VSS, H27 VSS, H28 VSS, J7 VSS, J11 VSS, J12 VSS, J13 VSS, J14 VSS, J15 VSS, J16 VSS, J17 VSS, J18 VSS, J20 VSS, J21 VSS, J26 VSS, J29 VSS, J30 VSS, K7 VSS, K11 VSS, K12 VSS, K13 VSS, K14 VSS, K15 VSS, K16 VSS, K17 VSS, K18 VSS, K20 VSS, K21 VSS, K22 VSS, K23 VSS, K24 VSS, K25 VSS, K27 VSS, K28 VSS, L7 VSS, L12 VSS, L14 VSS, L15 VSS, L16 VSS, L18 VSS, L20 VSS, L22 VSS, L23 VSS, L24 VSS, L26 VSS, L29 VSS, L30 VSS, M7 VSS, M12 VSS, M14 VSS, M15 VSS, M18 VSS, M19 VSS, M20 VSS, M23 VSS, M24 VSS, M25 VSS, M27 VSS, M28 VSS, N7 VSS, N11 VSS, N12 VSS, N13 VSS, N15 VSS, N16 VSS, N17 VSS, N21 VSS, N22 VSS, N26 VSS, N29 VSS, N30 VSS, P7 VSS, P8 VSS, P9 VSS, P10 VSS, P11 VSS, P12 VSS, P13 VSS, W1 VSS, W28 VSS, W29 VSS, W30 VSS, Y1 VSS, Y28 VSS
part L pins: A11 RSVD, E3 RSVD, K26 +MGTRAVCC, L17 VCC_PSPLL, L19 RSVD, L21 VCCO_PSDDR, M16 RSVD, M17 RSVD, M21 RSVD, M22 RSVD, M26 +MGTRAVTT, N18 RSVD, N19 RSVD, N20 RSVD, P16 RSVD, P17 RSVD, P21 RSVD, P22 RSVD, W27 RSVD, Y27 RSVD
